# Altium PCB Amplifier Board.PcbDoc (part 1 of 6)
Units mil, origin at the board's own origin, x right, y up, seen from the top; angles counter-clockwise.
Board outline 6000 x 2640 mil, 6 copper layers (Top Layer, GND, VCC, BASES, GND (Plane3), Bottom Layer), stack 63.9 mil thick; 884 components, 484 nets, 2029 pads, 464 vias.
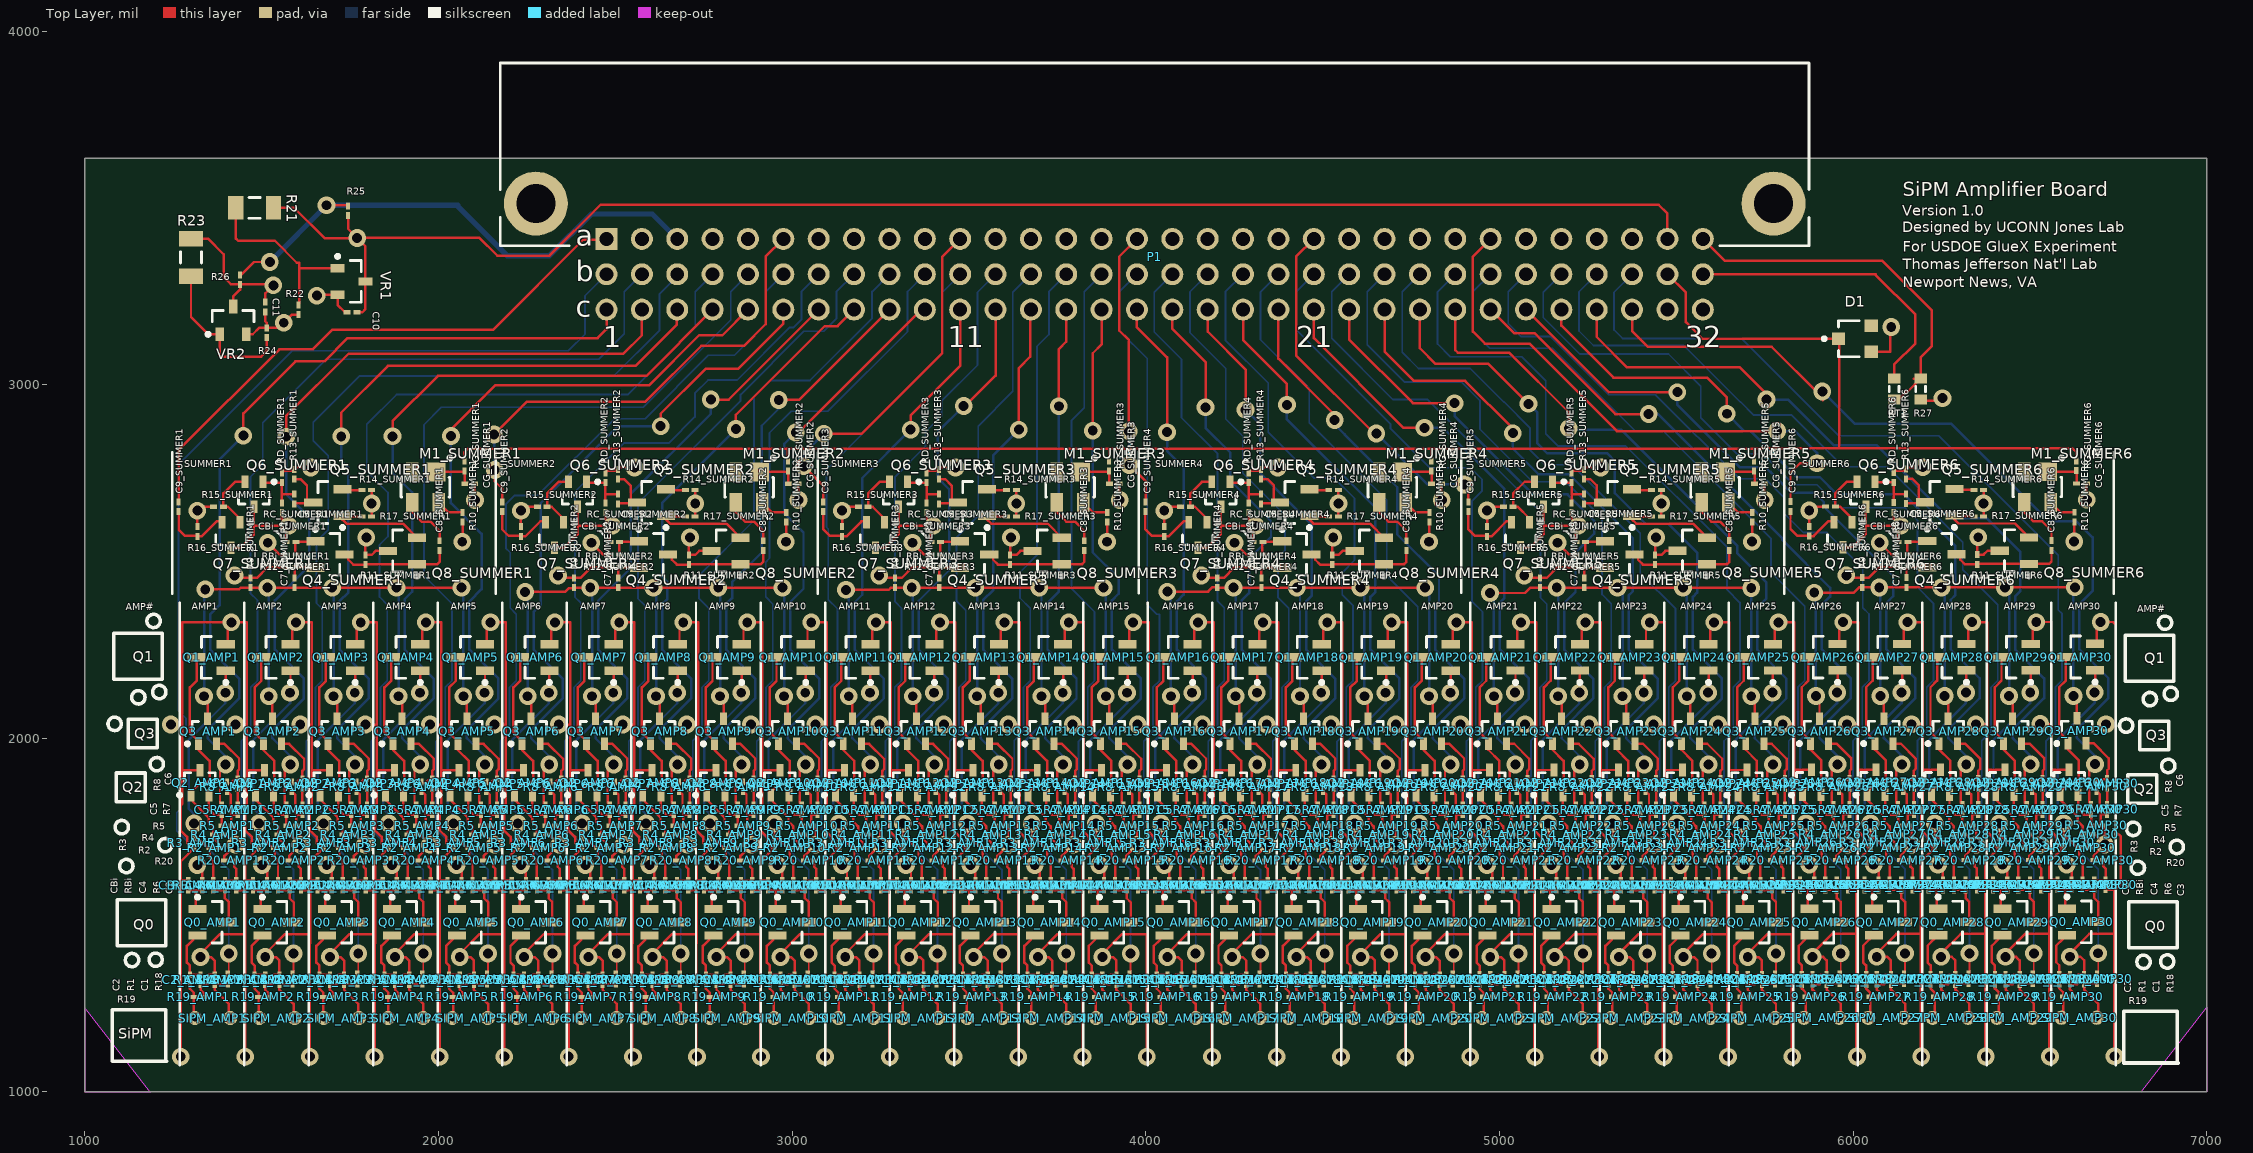
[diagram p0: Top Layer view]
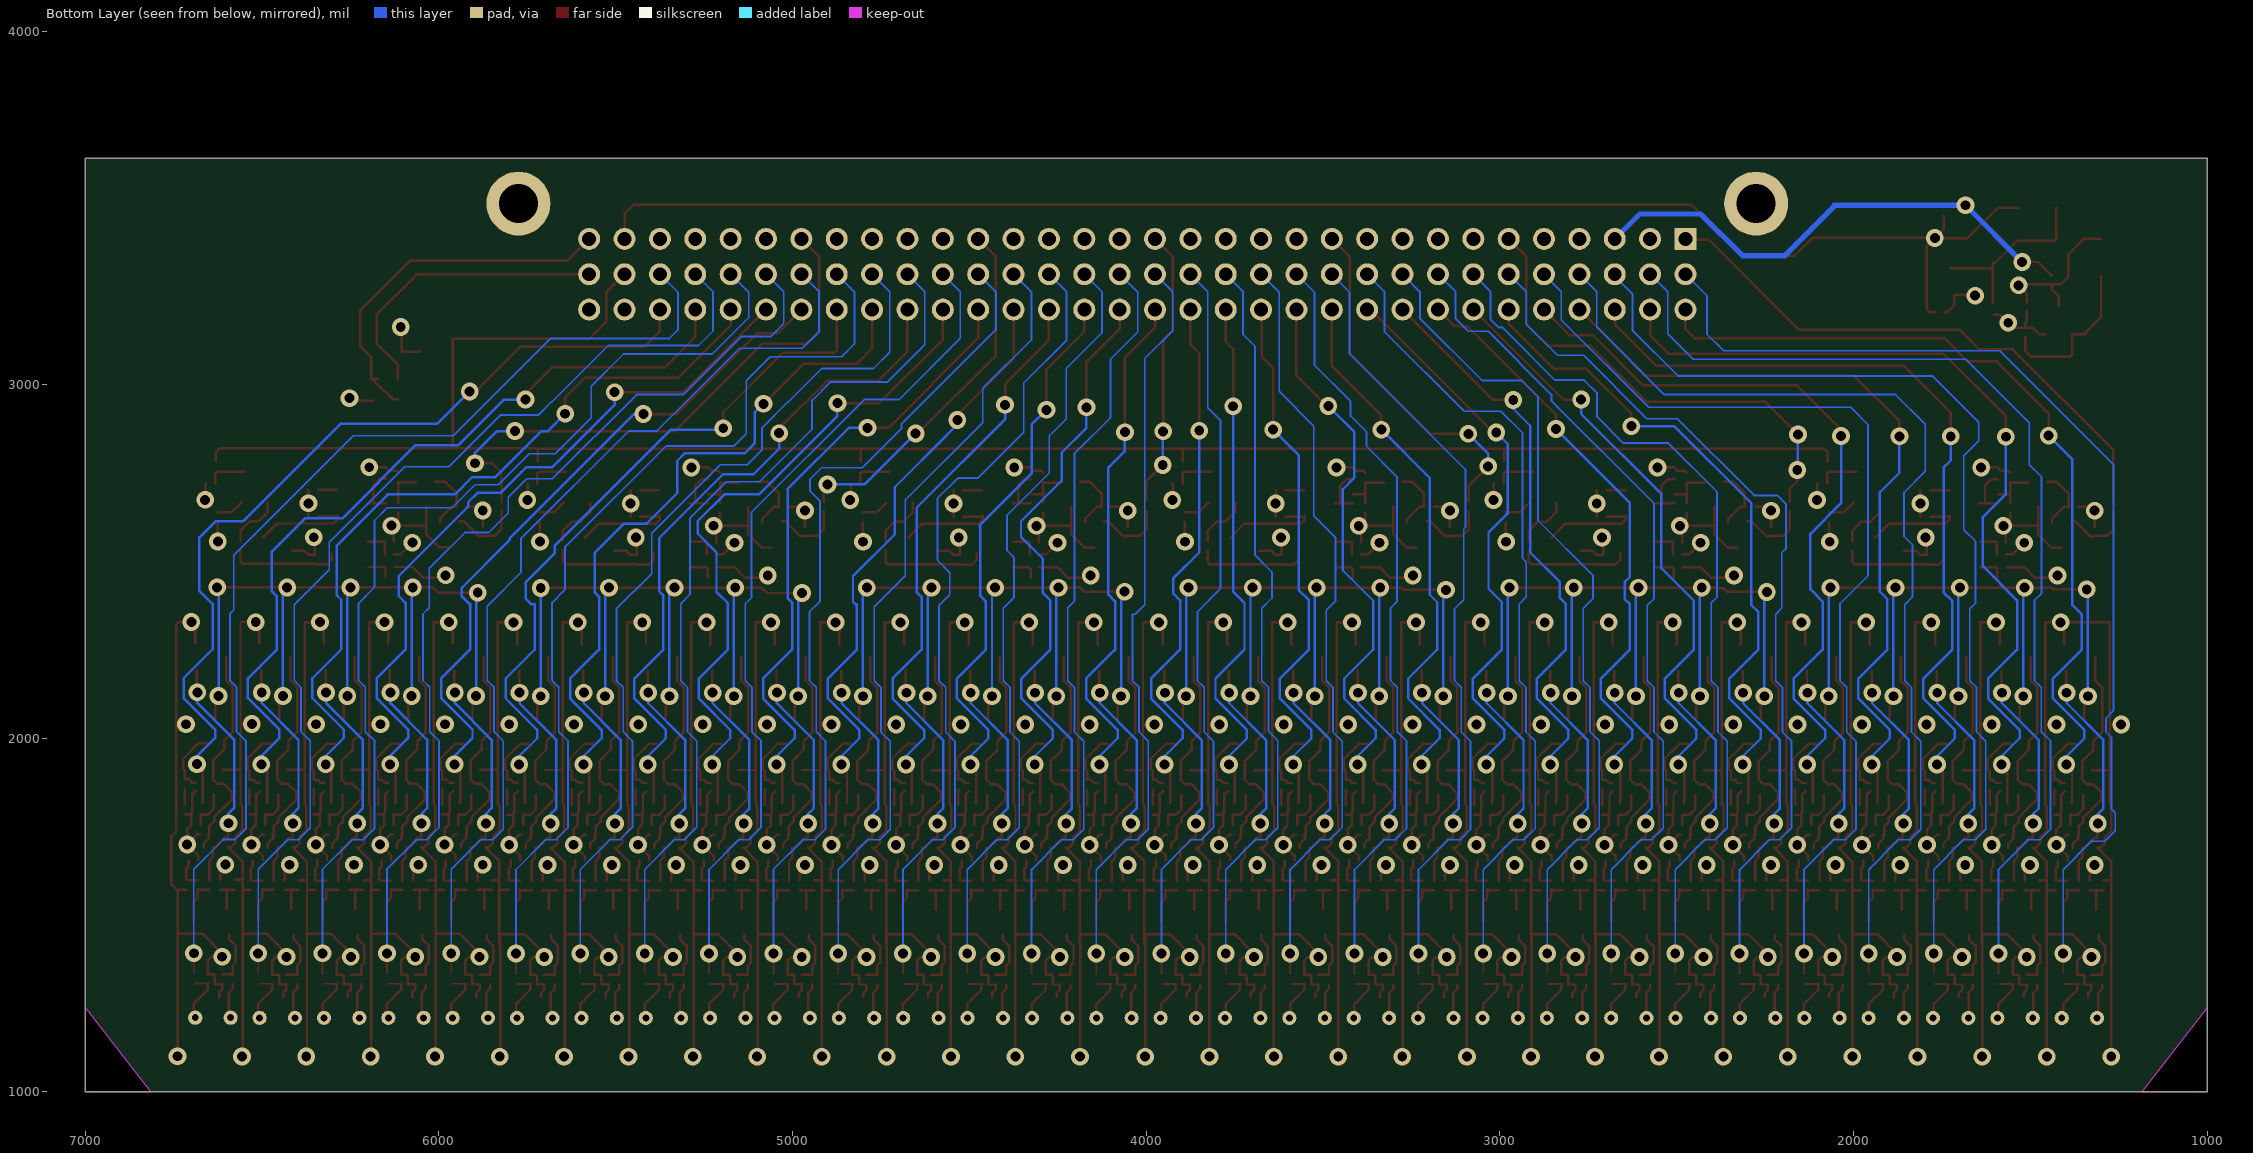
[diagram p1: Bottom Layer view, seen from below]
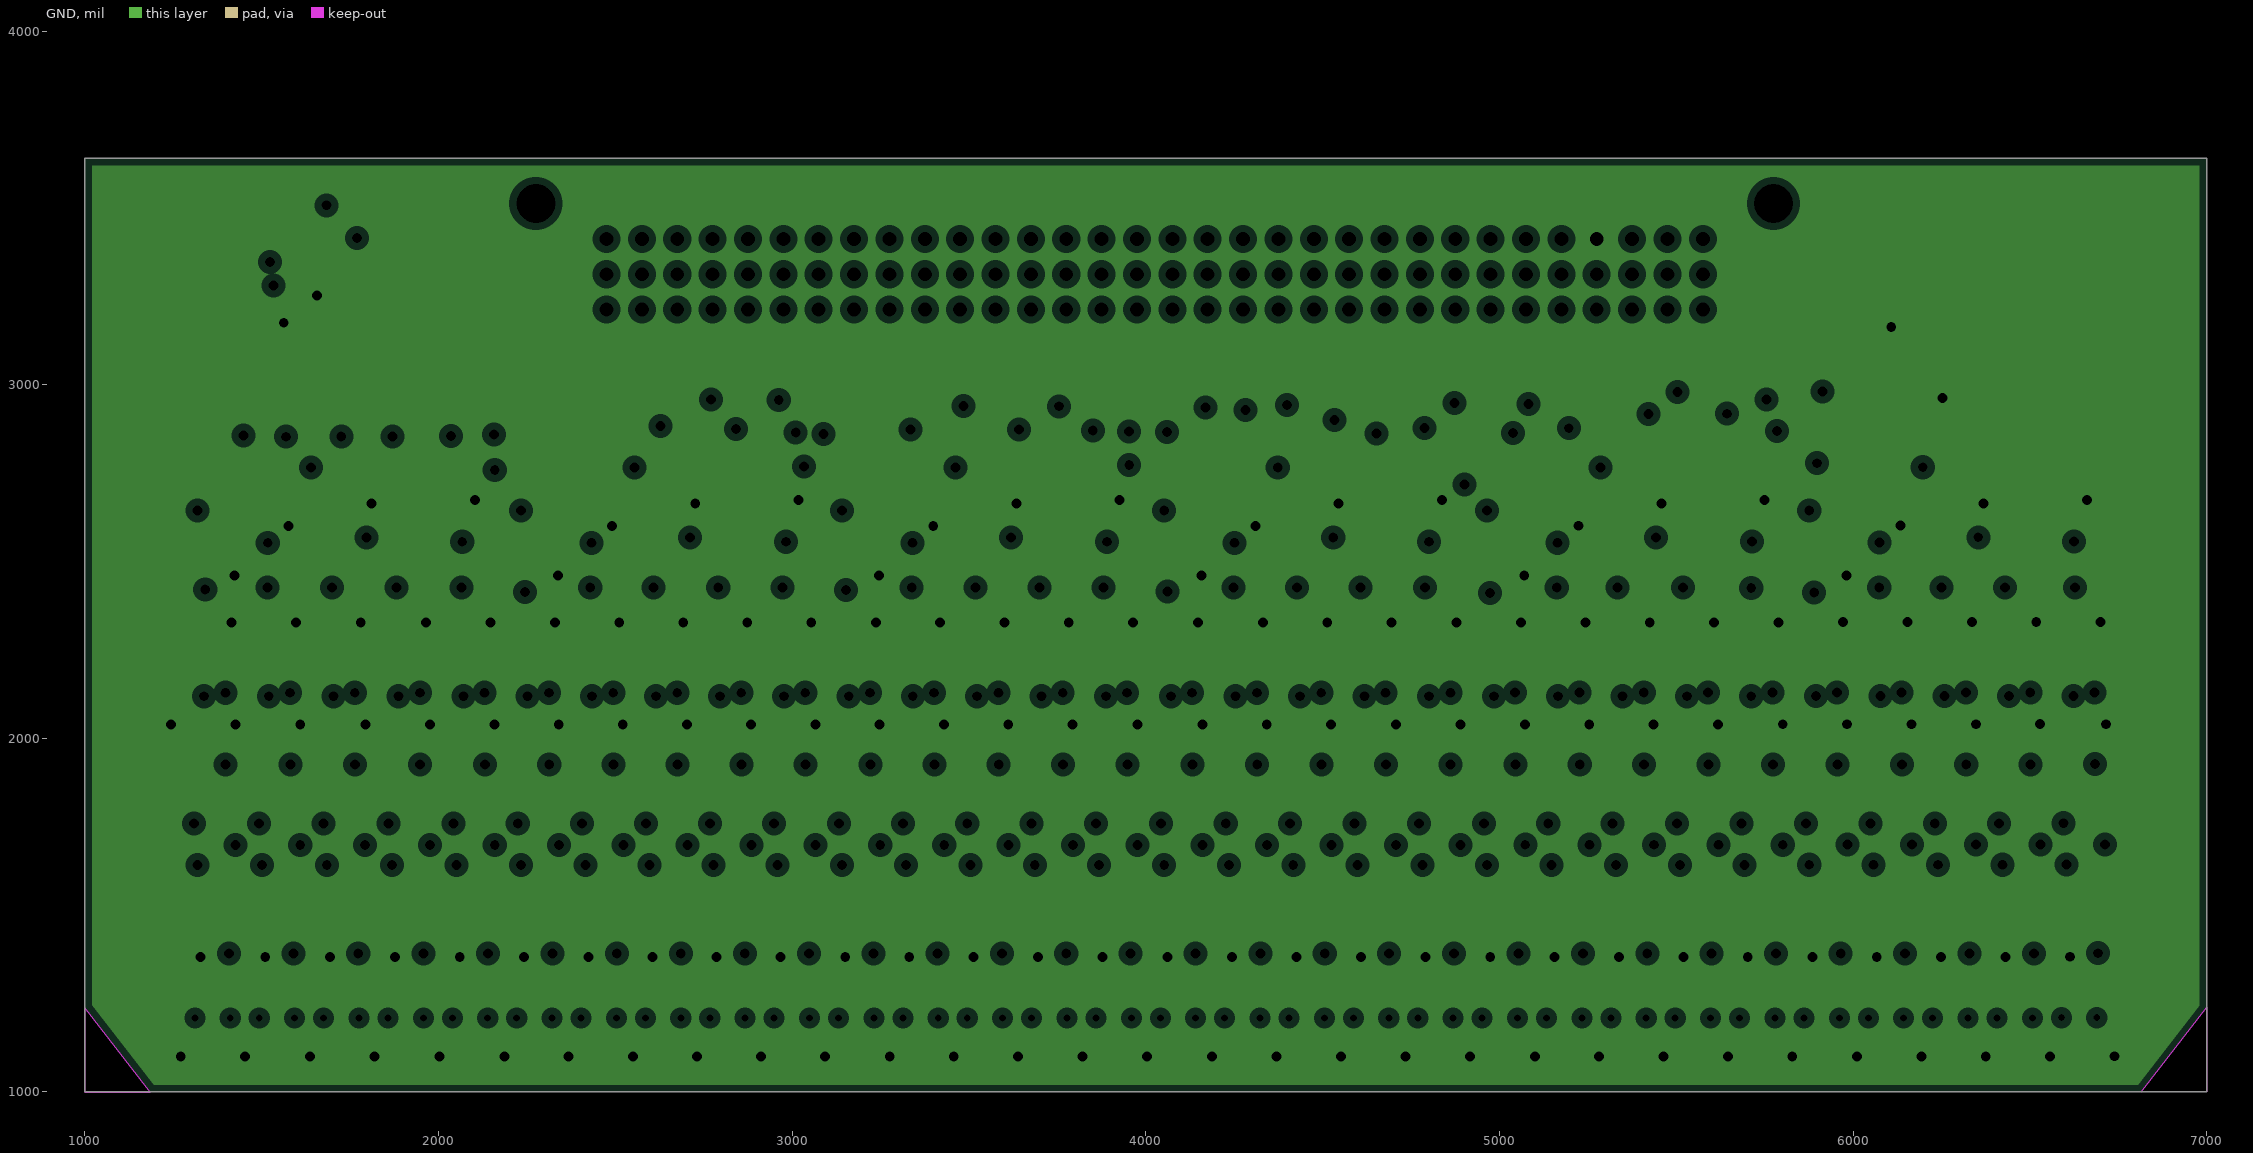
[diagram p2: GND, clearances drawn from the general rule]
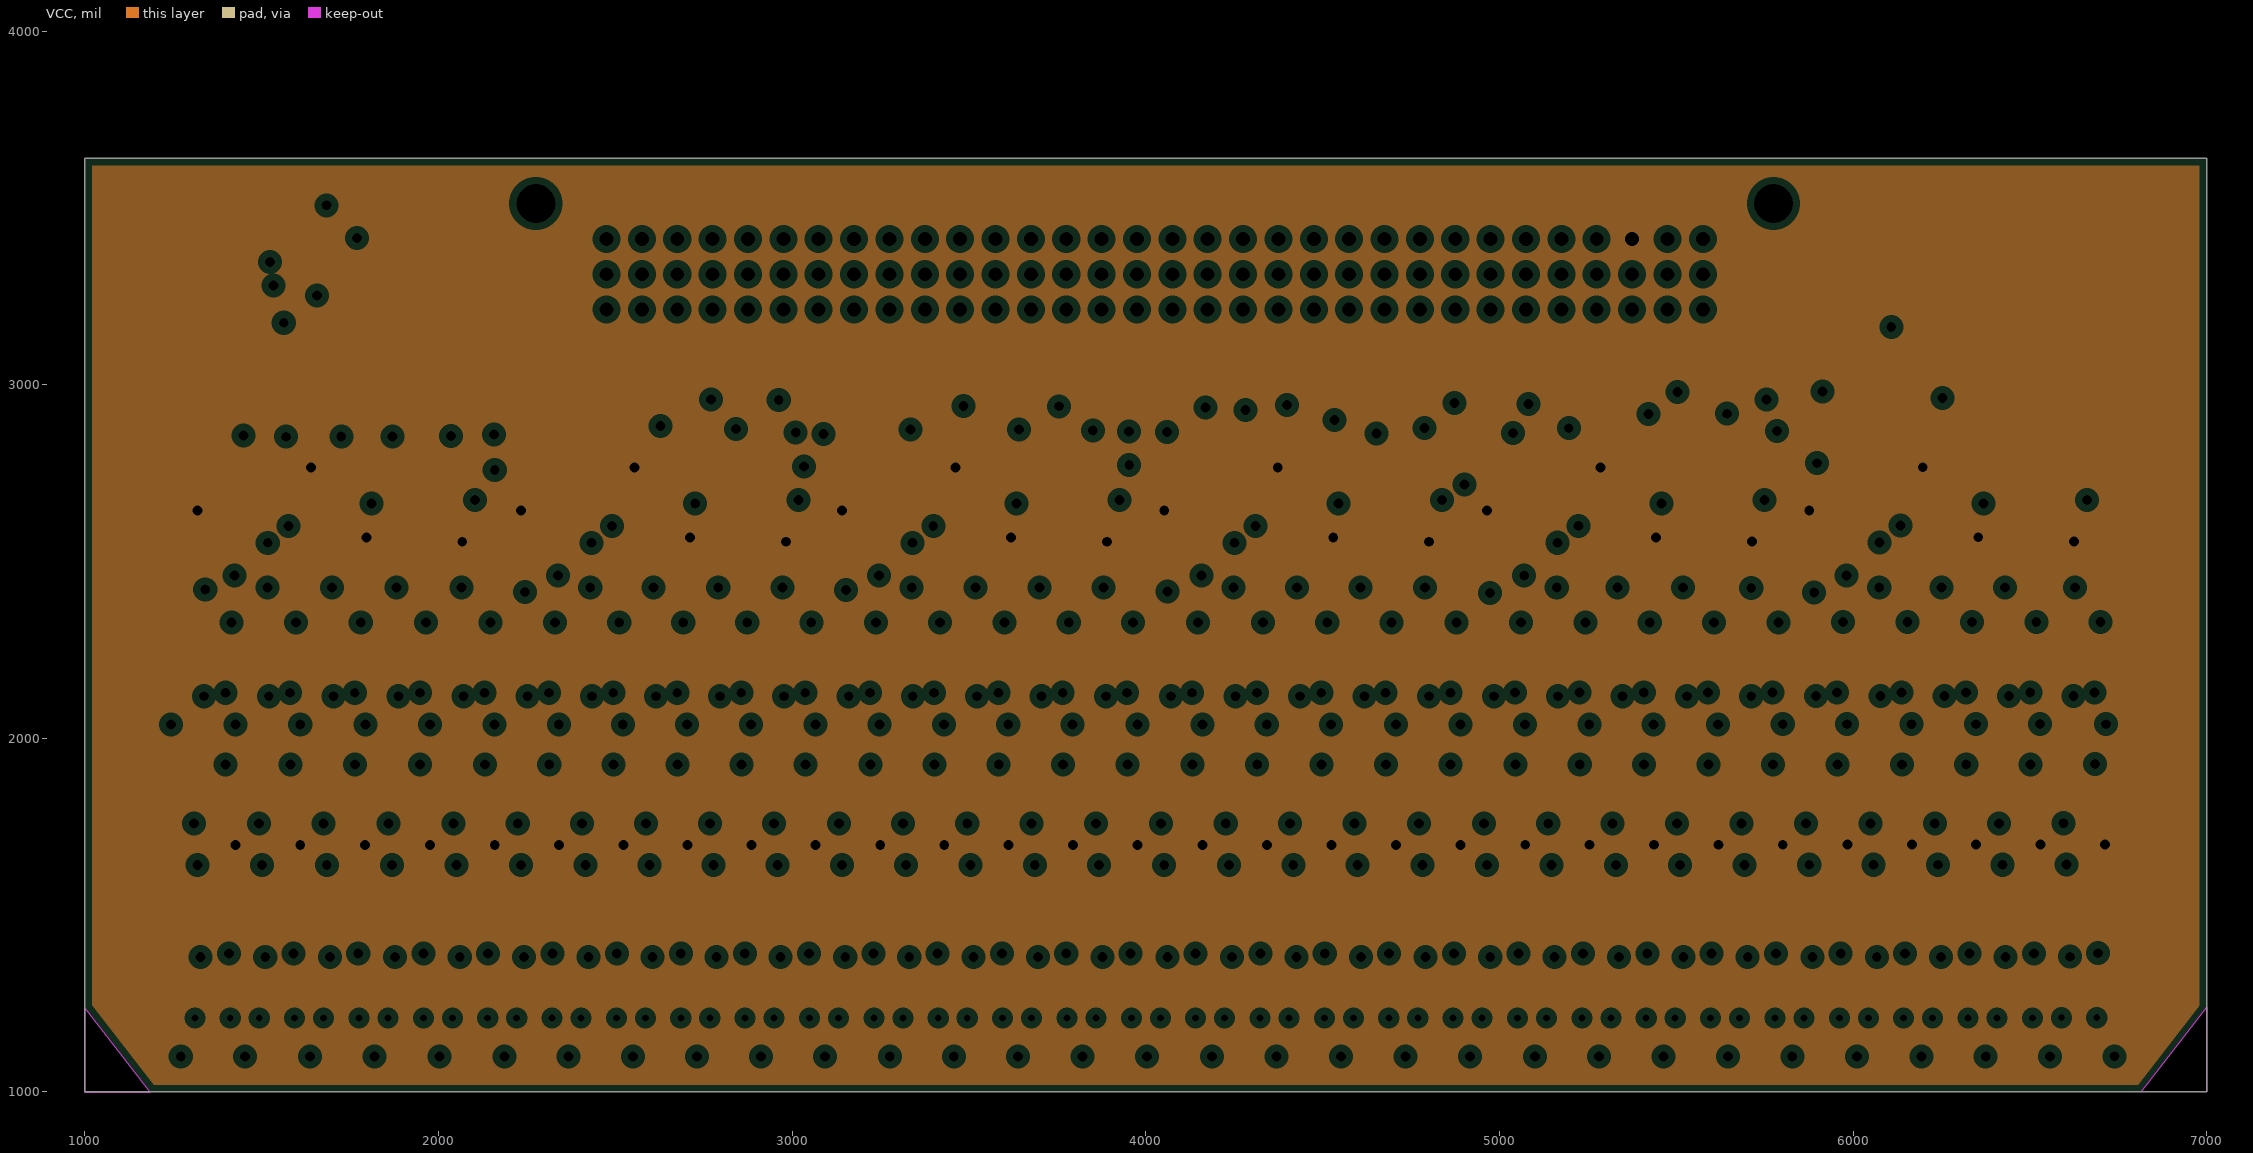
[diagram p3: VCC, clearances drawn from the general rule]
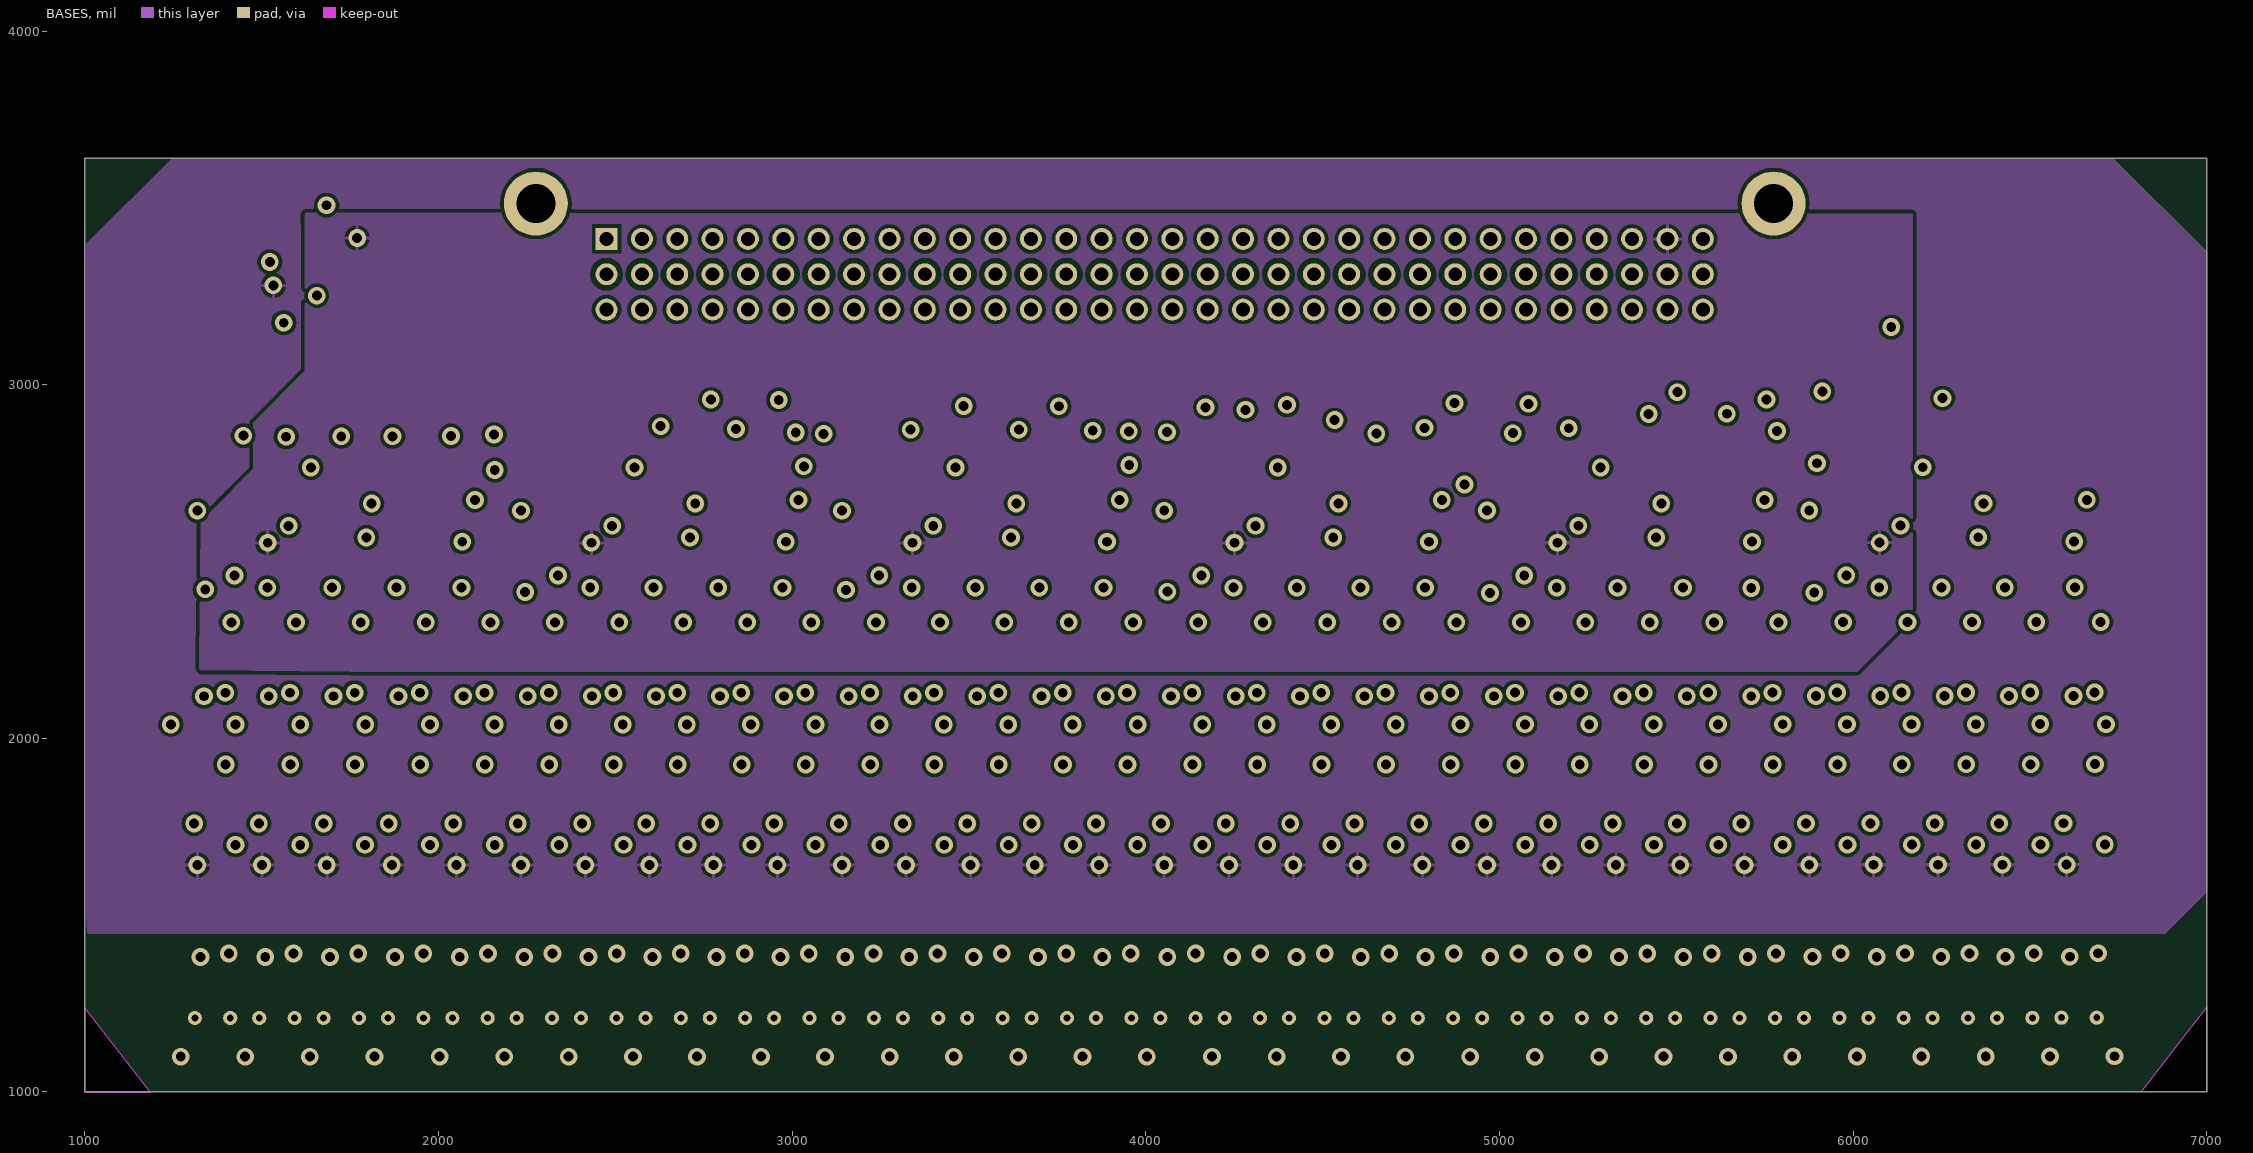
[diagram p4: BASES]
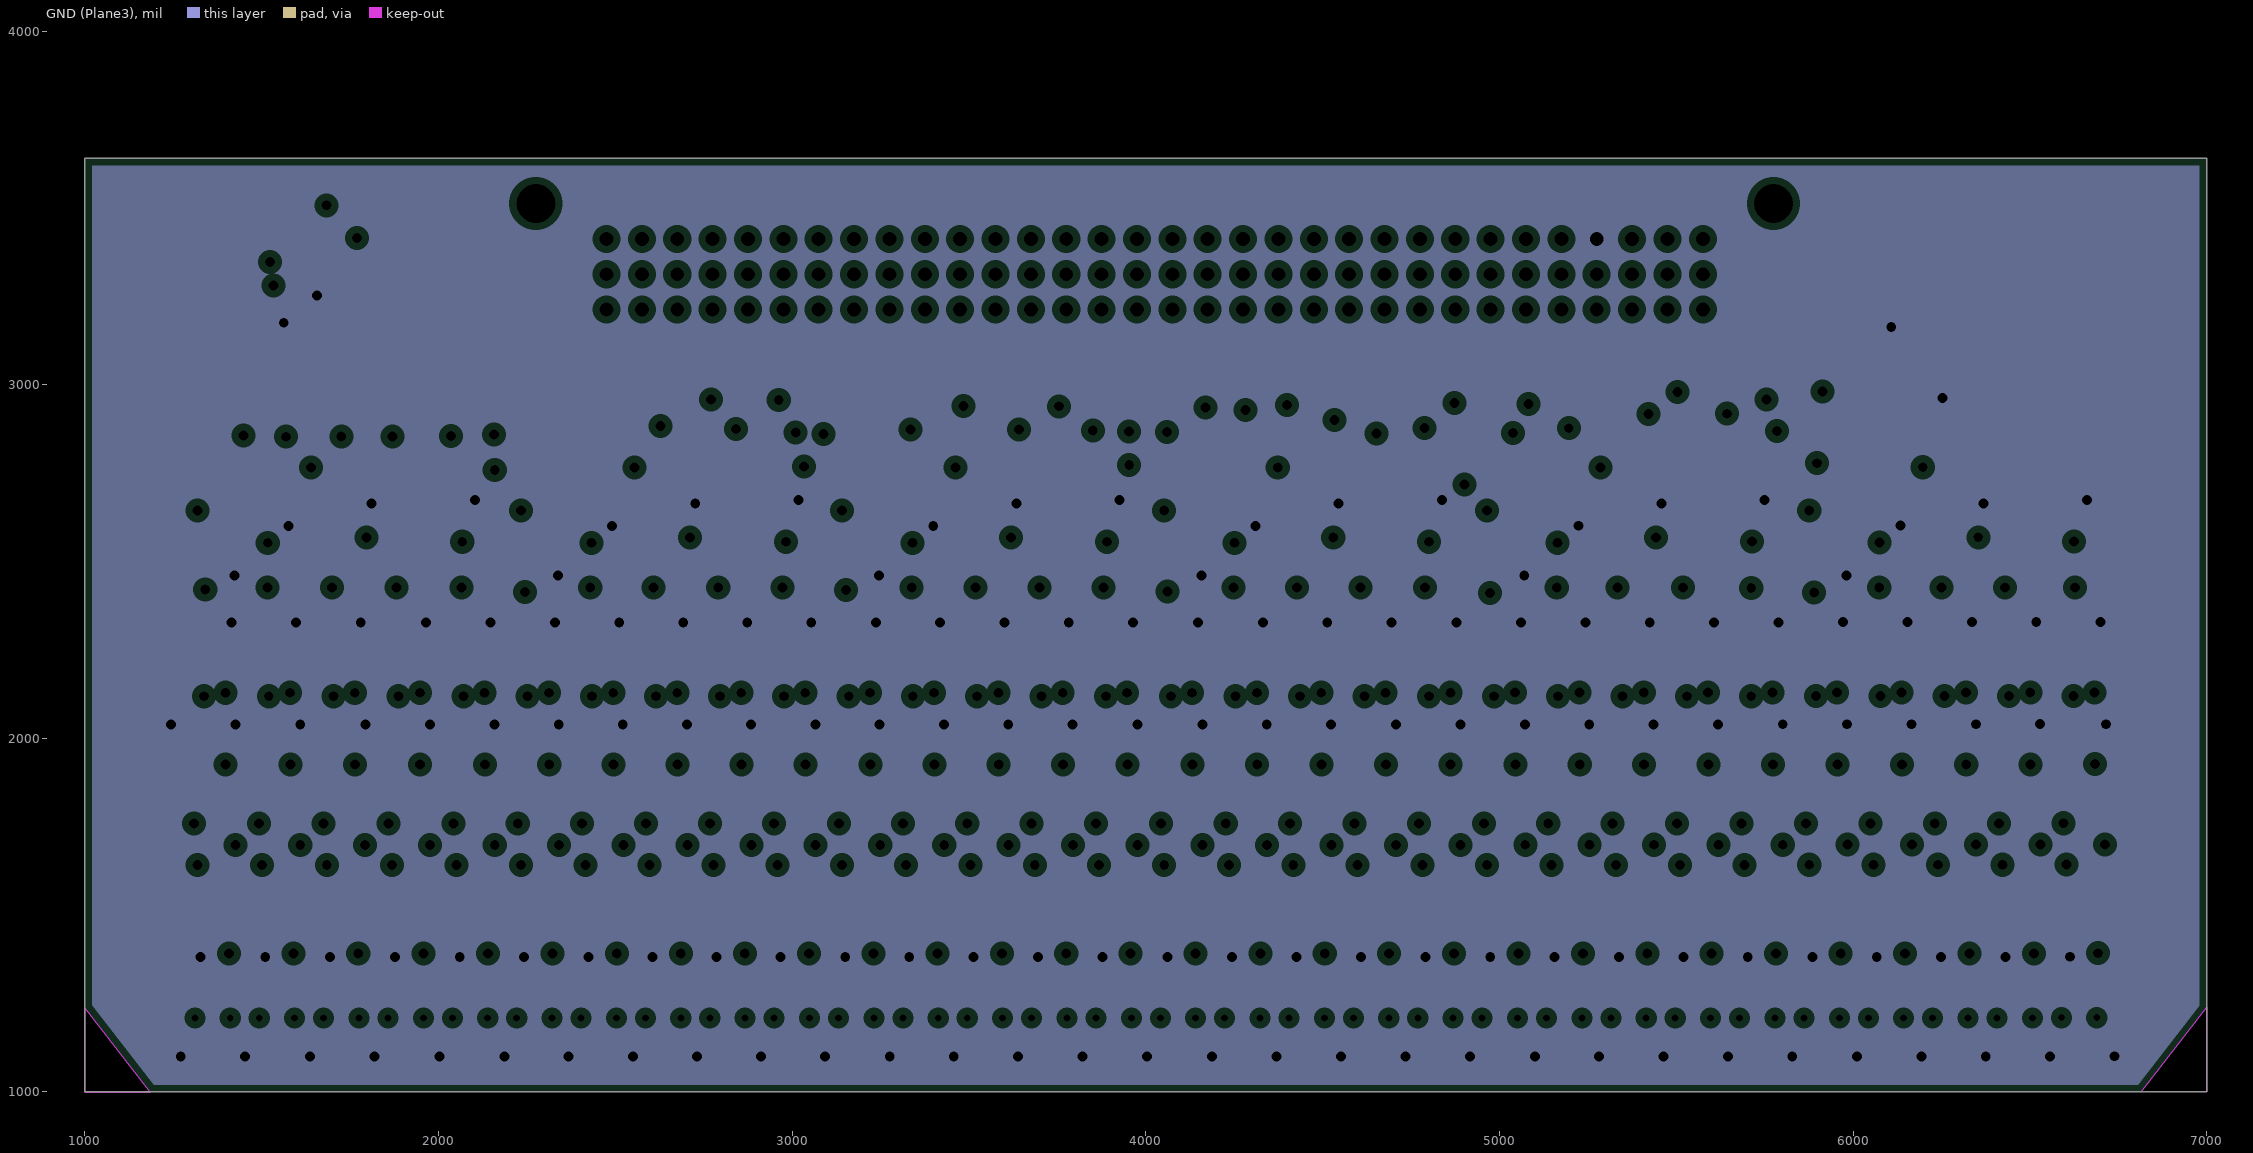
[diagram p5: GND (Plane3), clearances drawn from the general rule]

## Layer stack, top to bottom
Top Layer: signal copper 1.4
Dielectric: prepreg 5.1, FR-4, Dk 4.8
GND: plane copper 1.4, net GND
Dielectric: core 12.6, FR-4, Dk 4.8
VCC: plane copper 1.4, net VCC
Dielectric: prepreg 12.6, FR-4, Dk 4.8
BASES: signal copper 1.4
Dielectric: core 12.6, FR-4, Dk 4.8
GND (Plane3): plane copper 1.4, net GND
Dielectric: prepreg 12.6, FR-4, Dk 4.8
Bottom Layer: signal copper 1.4

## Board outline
1000,1000 7000,1000 7000,3640 1000,3640
cut-out: 1000,1238.5 1000,999.5 1185,999.5
cut-out: 7000.5,1239 7000.5,1000 6815.5,1000

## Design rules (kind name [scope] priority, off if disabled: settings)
Clearance Clearance_0201 [(HasFootprint('RESC0603L')) vs (HasFootprint('RESC0603L'))] p1: gap=6
Clearance Clearance_BIAS [InNetClass('BIAS')] p2: gap=15
Clearance Clearance_General [All] p3: gap=10
ComponentClearance [All] p1: gap=10 collisioncheckmode=3 verticalgap=10
HoleSize [All] p1: absolutevalues=TRUE maxlimit=120 minlimit=1 maxpercent=80.000 minpercent=20.000
PlaneClearance [All] p1: clearance=20
PlaneConnect [All] p1: planeconnectstyle=Relief reliefexpansion=20 reliefentries=4 reliefconductorwidth=10 reliefairgap=10
PolygonConnect [All] p1: connectstyle=Relief reliefconductorwidth=10 reliefentries=4 polygonreliefangle="90 Angle"
RoomDefinition THERMAL [InComponentClass('THERMAL')] p1: confinementstyle=ConfineIn formatcopy=TRUE lockcomponents=FALSE outline 6064,2900 6289,2900 6289,3110 6064,3110
RoomDefinition VREF [InComponentClass('VREF')] p2: confinementstyle=ConfineIn formatcopy=TRUE lockcomponents=FALSE outline 1207,3072 1894,3072 1894,3561 1207,3561
RoomDefinition AMP28 [InComponentClass('AMP28')] p3: confinementstyle=ConfineIn formatcopy=TRUE lockcomponents=FALSE outline 6164,1074.57 6384,1074.57 6384,2392.57 6164,2392.57
RoomDefinition AMP27 [InComponentClass('AMP27')] p4: confinementstyle=ConfineIn formatcopy=TRUE lockcomponents=FALSE outline 5982,1074.57 6202,1074.57 6202,2392.57 5982,2392.57
RoomDefinition AMP26 [InComponentClass('AMP26')] p5: confinementstyle=ConfineIn formatcopy=TRUE lockcomponents=FALSE outline 5800,1074.57 6020,1074.57 6020,2392.57 5800,2392.57
RoomDefinition AMP25 [InComponentClass('AMP25')] p6: confinementstyle=ConfineIn formatcopy=TRUE lockcomponents=FALSE outline 5617,1074.1 5837,1074.1 5837,2392.1 5617,2392.1
RoomDefinition AMP24 [InComponentClass('AMP24')] p7: confinementstyle=ConfineIn formatcopy=TRUE lockcomponents=FALSE outline 5435,1074.1 5655,1074.1 5655,2392.1 5435,2392.1
RoomDefinition AMP23 [InComponentClass('AMP23')] p8: confinementstyle=ConfineIn formatcopy=TRUE lockcomponents=FALSE outline 5253,1074.1 5473,1074.1 5473,2392.1 5253,2392.1
RoomDefinition AMP22 [InComponentClass('AMP22')] p9: confinementstyle=ConfineIn formatcopy=TRUE lockcomponents=FALSE outline 5071,1074.1 5291,1074.1 5291,2392.1 5071,2392.1
RoomDefinition AMP21 [InComponentClass('AMP21')] p10: confinementstyle=ConfineIn formatcopy=TRUE lockcomponents=FALSE outline 4889,1074.1 5109,1074.1 5109,2392.1 4889,2392.1
RoomDefinition AMP20 [InComponentClass('AMP20')] p11: confinementstyle=ConfineIn formatcopy=TRUE lockcomponents=FALSE outline 4706,1074 4926,1074 4926,2392 4706,2392
RoomDefinition AMP19 [InComponentClass('AMP19')] p12: confinementstyle=ConfineIn formatcopy=TRUE lockcomponents=FALSE outline 4523,1074 4743,1074 4743,2392 4523,2392
RoomDefinition AMP18 [InComponentClass('AMP18')] p13: confinementstyle=ConfineIn formatcopy=TRUE lockcomponents=FALSE outline 4341,1074 4561,1074 4561,2392 4341,2392
RoomDefinition AMP17 [InComponentClass('AMP17')] p14: confinementstyle=ConfineIn formatcopy=TRUE lockcomponents=FALSE outline 4159,1074 4379,1074 4379,2392 4159,2392
RoomDefinition AMP16 [InComponentClass('AMP16')] p15: confinementstyle=ConfineIn formatcopy=TRUE lockcomponents=FALSE outline 3976,1074 4196,1074 4196,2392 3976,2392
RoomDefinition AMP15 [InComponentClass('AMP15')] p16: confinementstyle=ConfineIn formatcopy=TRUE lockcomponents=FALSE outline 3792,1074 4012,1074 4012,2392 3792,2392
RoomDefinition AMP14 [InComponentClass('AMP14')] p17: confinementstyle=ConfineIn formatcopy=TRUE lockcomponents=FALSE outline 3610,1074 3830,1074 3830,2392 3610,2392
RoomDefinition AMP13 [InComponentClass('AMP13')] p18: confinementstyle=ConfineIn formatcopy=TRUE lockcomponents=FALSE outline 3428,1074 3648,1074 3648,2392 3428,2392
RoomDefinition AMP12 [InComponentClass('AMP12')] p19: confinementstyle=ConfineIn formatcopy=TRUE lockcomponents=FALSE outline 3246,1074 3466,1074 3466,2392 3246,2392
RoomDefinition AMP11 [InComponentClass('AMP11')] p20: confinementstyle=ConfineIn formatcopy=TRUE lockcomponents=FALSE outline 3065,1074 3285,1074 3285,2392 3065,2392
RoomDefinition AMP10 [InComponentClass('AMP10')] p21: confinementstyle=ConfineIn formatcopy=TRUE lockcomponents=FALSE outline 2882,1074 3102,1074 3102,2392 2882,2392
RoomDefinition AMP9 [InComponentClass('AMP9')] p22: confinementstyle=ConfineIn formatcopy=TRUE lockcomponents=FALSE outline 2701,1074 2921,1074 2921,2392 2701,2392
RoomDefinition AMP8 [InComponentClass('AMP8')] p23: confinementstyle=ConfineIn formatcopy=TRUE lockcomponents=FALSE outline 2520,1074 2740,1074 2740,2392 2520,2392
RoomDefinition AMP7 [InComponentClass('AMP7')] p24: confinementstyle=ConfineIn formatcopy=TRUE lockcomponents=FALSE outline 2339,1074 2559,1074 2559,2392 2339,2392
RoomDefinition AMP6 [InComponentClass('AMP6')] p25: confinementstyle=ConfineIn formatcopy=TRUE lockcomponents=FALSE outline 2157,1074 2377,1074 2377,2392 2157,2392
RoomDefinition AMP5 [InComponentClass('AMP5')] p26: confinementstyle=ConfineIn formatcopy=TRUE lockcomponents=FALSE outline 1975,1074 2195,1074 2195,2392 1975,2392
RoomDefinition AMP4 [InComponentClass('AMP4')] p27: confinementstyle=ConfineIn formatcopy=TRUE lockcomponents=FALSE outline 1792,1074 2012,1074 2012,2392 1792,2392
RoomDefinition AMP3 [InComponentClass('AMP3')] p28: confinementstyle=ConfineIn formatcopy=TRUE lockcomponents=FALSE outline 1608,1074 1828,1074 1828,2392 1608,2392
RoomDefinition AMP2 [InComponentClass('AMP2')] p29: confinementstyle=ConfineIn formatcopy=TRUE lockcomponents=TRUE outline 1425,1074 1645,1074 1645,2392 1425,2392
RoomDefinition AMP1 [InComponentClass('AMP1')] p30: confinementstyle=ConfineIn formatcopy=TRUE lockcomponents=FALSE outline 1242,1074 1462,1074 1462,2392 1242,2392
RoomDefinition AMP29 [InComponentClass('AMP29')] p31: confinementstyle=ConfineIn formatcopy=TRUE lockcomponents=FALSE outline 6346,1074.57 6566,1074.57 6566,2392.57 6346,2392.57
RoomDefinition SUMMER6 [InComponentClass('SUMMER6')] p32: confinementstyle=ConfineIn formatcopy=TRUE lockcomponents=FALSE outline 5800,2392.57 6753,2392.57 6753,2818.57 5800,2818.57
RoomDefinition SUMMER5 [InComponentClass('SUMMER5')] p33: confinementstyle=ConfineIn formatcopy=TRUE lockcomponents=FALSE outline 4889,2392.1 5842,2392.1 5842,2818.1 4889,2818.1
RoomDefinition SUMMER4 [InComponentClass('SUMMER4')] p34: confinementstyle=ConfineIn formatcopy=TRUE lockcomponents=FALSE outline 3976,2392 4929,2392 4929,2818 3976,2818
RoomDefinition SUMMER3 [InComponentClass('SUMMER3')] p35: confinementstyle=ConfineIn formatcopy=TRUE lockcomponents=FALSE outline 3065,2392 4018,2392 4018,2818 3065,2818
RoomDefinition SUMMER2 [InComponentClass('SUMMER2')] p36: confinementstyle=ConfineIn formatcopy=TRUE lockcomponents=FALSE outline 2157,2392 3110,2392 3110,2818 2157,2818
RoomDefinition AMP30 [InComponentClass('AMP30')] p37: confinementstyle=ConfineIn formatcopy=FALSE lockcomponents=FALSE outline 6528,1075 6748,1075 6748,2393 6528,2393
RoomDefinition Main [InComponentClass('Main')] p38: confinementstyle=ConfineIn formatcopy=TRUE lockcomponents=FALSE outline 6141,2982 6141,4174 1926,4174 1926,2982
RoomDefinition SUMMER1 [InComponentClass('SUMMER1')] p39: confinementstyle=ConfineIn formatcopy=TRUE lockcomponents=FALSE outline 1242,2392 2195,2392 2195,2818 1242,2818
RoutingVias [All] p1: holewidth=28 width=50 viastyle="Through Hole" minholewidth=28 minwidth=50 maxholewidth=28 maxwidth=50
SolderMaskExpansion [All] p1: expansion=4
TestPointUsage [All] p1: valid=0 allowmultiple=FALSE
Testpoint [All] p1: side=15 testpointundercomponent=TRUE minsize=40 maxsize=100 preferedsize=60 minholesize=0 maxholesize=40 preferedholesize=32 testpointgrid=1 style=1023 order=0123456789
Width Width_BIAS [InNetClass('BIAS')] p1: maxlimit=10 minlimit=4 preferedwidth=7
Width Width_+5V [InNet('+5V')] p2: maxlimit=20 minlimit=5.09 preferedwidth=15 midlayer1_minwidth=0 midlayer1_maxwidth=0 midlayer1_prefwidth=0 minimp=50.000000 maximp=60.000000 favimp=50.000000
15 further rules are at their usual default settings.

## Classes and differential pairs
channel class Summer: SUMMER1 SUMMER2 SUMMER3 SUMMER4 SUMMER5 SUMMER6
channel class Amplifier: AMP1 AMP2 AMP3 AMP4 AMP5 AMP6 AMP7 AMP8 AMP9 AMP10 AMP11 AMP12 AMP13 AMP14 AMP15 AMP16 AMP17 AMP18 AMP19 AMP20 AMP21 AMP22 AMP23 AMP24 AMP25 AMP26 AMP27 AMP28 AMP29 AMP30
component class VREF: C10 C11 R21 R22 R23 R24 R25 R26 VR1 VR2
component class SUMMER6: C5_SUMMER6 C7_SUMMER6 C8_SUMMER6 C9_SUMMER6 CBi_SUMMER6 CG_SUMMER6 M1_SUMMER6 Q4_SUMMER6 Q5_SUMMER6 Q6_SUMMER6 Q7_SUMMER6 Q8_SUMMER6 R9_SUMMER6 R10_SUMMER6 R11_SUMMER6 R12_SUMMER6 R13_SUMMER6 R14_SUMMER6 R15_SUMMER6 R16_SUMMER6 R17_SUMMER6 RBi_SUMMER6 RC_SUMMER6 RD_SUMMER6 RG_SUMMER6
component class SUMMER5: C5_SUMMER5 C7_SUMMER5 C8_SUMMER5 C9_SUMMER5 CBi_SUMMER5 CG_SUMMER5 M1_SUMMER5 Q4_SUMMER5 Q5_SUMMER5 Q6_SUMMER5 Q7_SUMMER5 Q8_SUMMER5 R9_SUMMER5 R10_SUMMER5 R11_SUMMER5 R12_SUMMER5 R13_SUMMER5 R14_SUMMER5 R15_SUMMER5 R16_SUMMER5 R17_SUMMER5 RBi_SUMMER5 RC_SUMMER5 RD_SUMMER5 RG_SUMMER5
component class SUMMER4: C5_SUMMER4 C7_SUMMER4 C8_SUMMER4 C9_SUMMER4 CBi_SUMMER4 CG_SUMMER4 M1_SUMMER4 Q4_SUMMER4 Q5_SUMMER4 Q6_SUMMER4 Q7_SUMMER4 Q8_SUMMER4 R9_SUMMER4 R10_SUMMER4 R11_SUMMER4 R12_SUMMER4 R13_SUMMER4 R14_SUMMER4 R15_SUMMER4 R16_SUMMER4 R17_SUMMER4 RBi_SUMMER4 RC_SUMMER4 RD_SUMMER4 RG_SUMMER4
component class SUMMER3: C5_SUMMER3 C7_SUMMER3 C8_SUMMER3 C9_SUMMER3 CBi_SUMMER3 CG_SUMMER3 M1_SUMMER3 Q4_SUMMER3 Q5_SUMMER3 Q6_SUMMER3 Q7_SUMMER3 Q8_SUMMER3 R9_SUMMER3 R10_SUMMER3 R11_SUMMER3 R12_SUMMER3 R13_SUMMER3 R14_SUMMER3 R15_SUMMER3 R16_SUMMER3 R17_SUMMER3 RBi_SUMMER3 RC_SUMMER3 RD_SUMMER3 RG_SUMMER3
component class SUMMER2: C5_SUMMER2 C7_SUMMER2 C8_SUMMER2 C9_SUMMER2 CBi_SUMMER2 CG_SUMMER2 M1_SUMMER2 Q4_SUMMER2 Q5_SUMMER2 Q6_SUMMER2 Q7_SUMMER2 Q8_SUMMER2 R9_SUMMER2 R10_SUMMER2 R11_SUMMER2 R12_SUMMER2 R13_SUMMER2 R14_SUMMER2 R15_SUMMER2 R16_SUMMER2 R17_SUMMER2 RBi_SUMMER2 RC_SUMMER2 RD_SUMMER2 RG_SUMMER2
component class SUMMER1: C5_SUMMER1 C7_SUMMER1 C8_SUMMER1 C9_SUMMER1 CBi_SUMMER1 CG_SUMMER1 M1_SUMMER1 Q4_SUMMER1 Q5_SUMMER1 Q6_SUMMER1 Q7_SUMMER1 Q8_SUMMER1 R9_SUMMER1 R10_SUMMER1 R11_SUMMER1 R12_SUMMER1 R13_SUMMER1 R14_SUMMER1 R15_SUMMER1 R16_SUMMER1 R17_SUMMER1 RBi_SUMMER1 RC_SUMMER1 RD_SUMMER1 RG_SUMMER1
component class Main: D1 P1
component class AMP30: C1_AMP30 C2_AMP30 C3_AMP30 C4_AMP30 C5_AMP30 C6_AMP30 CBi_AMP30 Q0_AMP30 Q1_AMP30 Q2_AMP30 Q3_AMP30 R1_AMP30 R2_AMP30 R3_AMP30 R4_AMP30 R5_AMP30 R6_AMP30 R7_AMP30 R8_AMP30 R18_AMP30 R19_AMP30 R20_AMP30 RBi_AMP30 SIPM_AMP30
component class AMP29: C1_AMP29 C2_AMP29 C3_AMP29 C4_AMP29 C5_AMP29 C6_AMP29 CBi_AMP29 Q0_AMP29 Q1_AMP29 Q2_AMP29 Q3_AMP29 R1_AMP29 R2_AMP29 R3_AMP29 R4_AMP29 R5_AMP29 R6_AMP29 R7_AMP29 R8_AMP29 R18_AMP29 R19_AMP29 R20_AMP29 RBi_AMP29 SIPM_AMP29
component class AMP28: C1_AMP28 C2_AMP28 C3_AMP28 C4_AMP28 C5_AMP28 C6_AMP28 CBi_AMP28 Q0_AMP28 Q1_AMP28 Q2_AMP28 Q3_AMP28 R1_AMP28 R2_AMP28 R3_AMP28 R4_AMP28 R5_AMP28 R6_AMP28 R7_AMP28 R8_AMP28 R18_AMP28 R19_AMP28 R20_AMP28 RBi_AMP28 SIPM_AMP28
component class AMP27: C1_AMP27 C2_AMP27 C3_AMP27 C4_AMP27 C5_AMP27 C6_AMP27 CBi_AMP27 Q0_AMP27 Q1_AMP27 Q2_AMP27 Q3_AMP27 R1_AMP27 R2_AMP27 R3_AMP27 R4_AMP27 R5_AMP27 R6_AMP27 R7_AMP27 R8_AMP27 R18_AMP27 R19_AMP27 R20_AMP27 RBi_AMP27 SIPM_AMP27
component class AMP26: C1_AMP26 C2_AMP26 C3_AMP26 C4_AMP26 C5_AMP26 C6_AMP26 CBi_AMP26 Q0_AMP26 Q1_AMP26 Q2_AMP26 Q3_AMP26 R1_AMP26 R2_AMP26 R3_AMP26 R4_AMP26 R5_AMP26 R6_AMP26 R7_AMP26 R8_AMP26 R18_AMP26 R19_AMP26 R20_AMP26 RBi_AMP26 SIPM_AMP26
component class AMP25: C1_AMP25 C2_AMP25 C3_AMP25 C4_AMP25 C5_AMP25 C6_AMP25 CBi_AMP25 Q0_AMP25 Q1_AMP25 Q2_AMP25 Q3_AMP25 R1_AMP25 R2_AMP25 R3_AMP25 R4_AMP25 R5_AMP25 R6_AMP25 R7_AMP25 R8_AMP25 R18_AMP25 R19_AMP25 R20_AMP25 RBi_AMP25 SIPM_AMP25
component class AMP24: C1_AMP24 C2_AMP24 C3_AMP24 C4_AMP24 C5_AMP24 C6_AMP24 CBi_AMP24 Q0_AMP24 Q1_AMP24 Q2_AMP24 Q3_AMP24 R1_AMP24 R2_AMP24 R3_AMP24 R4_AMP24 R5_AMP24 R6_AMP24 R7_AMP24 R8_AMP24 R18_AMP24 R19_AMP24 R20_AMP24 RBi_AMP24 SIPM_AMP24
component class AMP23: C1_AMP23 C2_AMP23 C3_AMP23 C4_AMP23 C5_AMP23 C6_AMP23 CBi_AMP23 Q0_AMP23 Q1_AMP23 Q2_AMP23 Q3_AMP23 R1_AMP23 R2_AMP23 R3_AMP23 R4_AMP23 R5_AMP23 R6_AMP23 R7_AMP23 R8_AMP23 R18_AMP23 R19_AMP23 R20_AMP23 RBi_AMP23 SIPM_AMP23
component class AMP22: C1_AMP22 C2_AMP22 C3_AMP22 C4_AMP22 C5_AMP22 C6_AMP22 CBi_AMP22 Q0_AMP22 Q1_AMP22 Q2_AMP22 Q3_AMP22 R1_AMP22 R2_AMP22 R3_AMP22 R4_AMP22 R5_AMP22 R6_AMP22 R7_AMP22 R8_AMP22 R18_AMP22 R19_AMP22 R20_AMP22 RBi_AMP22 SIPM_AMP22
component class AMP21: C1_AMP21 C2_AMP21 C3_AMP21 C4_AMP21 C5_AMP21 C6_AMP21 CBi_AMP21 Q0_AMP21 Q1_AMP21 Q2_AMP21 Q3_AMP21 R1_AMP21 R2_AMP21 R3_AMP21 R4_AMP21 R5_AMP21 R6_AMP21 R7_AMP21 R8_AMP21 R18_AMP21 R19_AMP21 R20_AMP21 RBi_AMP21 SIPM_AMP21
component class AMP20: C1_AMP20 C2_AMP20 C3_AMP20 C4_AMP20 C5_AMP20 C6_AMP20 CBi_AMP20 Q0_AMP20 Q1_AMP20 Q2_AMP20 Q3_AMP20 R1_AMP20 R2_AMP20 R3_AMP20 R4_AMP20 R5_AMP20 R6_AMP20 R7_AMP20 R8_AMP20 R18_AMP20 R19_AMP20 R20_AMP20 RBi_AMP20 SIPM_AMP20
component class AMP19: C1_AMP19 C2_AMP19 C3_AMP19 C4_AMP19 C5_AMP19 C6_AMP19 CBi_AMP19 Q0_AMP19 Q1_AMP19 Q2_AMP19 Q3_AMP19 R1_AMP19 R2_AMP19 R3_AMP19 R4_AMP19 R5_AMP19 R6_AMP19 R7_AMP19 R8_AMP19 R18_AMP19 R19_AMP19 R20_AMP19 RBi_AMP19 SIPM_AMP19
component class AMP18: C1_AMP18 C2_AMP18 C3_AMP18 C4_AMP18 C5_AMP18 C6_AMP18 CBi_AMP18 Q0_AMP18 Q1_AMP18 Q2_AMP18 Q3_AMP18 R1_AMP18 R2_AMP18 R3_AMP18 R4_AMP18 R5_AMP18 R6_AMP18 R7_AMP18 R8_AMP18 R18_AMP18 R19_AMP18 R20_AMP18 RBi_AMP18 SIPM_AMP18
component class AMP17: C1_AMP17 C2_AMP17 C3_AMP17 C4_AMP17 C5_AMP17 C6_AMP17 CBi_AMP17 Q0_AMP17 Q1_AMP17 Q2_AMP17 Q3_AMP17 R1_AMP17 R2_AMP17 R3_AMP17 R4_AMP17 R5_AMP17 R6_AMP17 R7_AMP17 R8_AMP17 R18_AMP17 R19_AMP17 R20_AMP17 RBi_AMP17 SIPM_AMP17
component class AMP16: C1_AMP16 C2_AMP16 C3_AMP16 C4_AMP16 C5_AMP16 C6_AMP16 CBi_AMP16 Q0_AMP16 Q1_AMP16 Q2_AMP16 Q3_AMP16 R1_AMP16 R2_AMP16 R3_AMP16 R4_AMP16 R5_AMP16 R6_AMP16 R7_AMP16 R8_AMP16 R18_AMP16 R19_AMP16 R20_AMP16 RBi_AMP16 SIPM_AMP16
component class AMP15: C1_AMP15 C2_AMP15 C3_AMP15 C4_AMP15 C5_AMP15 C6_AMP15 CBi_AMP15 Q0_AMP15 Q1_AMP15 Q2_AMP15 Q3_AMP15 R1_AMP15 R2_AMP15 R3_AMP15 R4_AMP15 R5_AMP15 R6_AMP15 R7_AMP15 R8_AMP15 R18_AMP15 R19_AMP15 R20_AMP15 RBi_AMP15 SIPM_AMP15
component class AMP14: C1_AMP14 C2_AMP14 C3_AMP14 C4_AMP14 C5_AMP14 C6_AMP14 CBi_AMP14 Q0_AMP14 Q1_AMP14 Q2_AMP14 Q3_AMP14 R1_AMP14 R2_AMP14 R3_AMP14 R4_AMP14 R5_AMP14 R6_AMP14 R7_AMP14 R8_AMP14 R18_AMP14 R19_AMP14 R20_AMP14 RBi_AMP14 SIPM_AMP14
component class AMP13: C1_AMP13 C2_AMP13 C3_AMP13 C4_AMP13 C5_AMP13 C6_AMP13 CBi_AMP13 Q0_AMP13 Q1_AMP13 Q2_AMP13 Q3_AMP13 R1_AMP13 R2_AMP13 R3_AMP13 R4_AMP13 R5_AMP13 R6_AMP13 R7_AMP13 R8_AMP13 R18_AMP13 R19_AMP13 R20_AMP13 RBi_AMP13 SIPM_AMP13
component class AMP12: C1_AMP12 C2_AMP12 C3_AMP12 C4_AMP12 C5_AMP12 C6_AMP12 CBi_AMP12 Q0_AMP12 Q1_AMP12 Q2_AMP12 Q3_AMP12 R1_AMP12 R2_AMP12 R3_AMP12 R4_AMP12 R5_AMP12 R6_AMP12 R7_AMP12 R8_AMP12 R18_AMP12 R19_AMP12 R20_AMP12 RBi_AMP12 SIPM_AMP12
component class AMP11: C1_AMP11 C2_AMP11 C3_AMP11 C4_AMP11 C5_AMP11 C6_AMP11 CBi_AMP11 Q0_AMP11 Q1_AMP11 Q2_AMP11 Q3_AMP11 R1_AMP11 R2_AMP11 R3_AMP11 R4_AMP11 R5_AMP11 R6_AMP11 R7_AMP11 R8_AMP11 R18_AMP11 R19_AMP11 R20_AMP11 RBi_AMP11 SIPM_AMP11
component class AMP10: C1_AMP10 C2_AMP10 C3_AMP10 C4_AMP10 C5_AMP10 C6_AMP10 CBi_AMP10 Q0_AMP10 Q1_AMP10 Q2_AMP10 Q3_AMP10 R1_AMP10 R2_AMP10 R3_AMP10 R4_AMP10 R5_AMP10 R6_AMP10 R7_AMP10 R8_AMP10 R18_AMP10 R19_AMP10 R20_AMP10 RBi_AMP10 SIPM_AMP10
component class AMP9: C1_AMP9 C2_AMP9 C3_AMP9 C4_AMP9 C5_AMP9 C6_AMP9 CBi_AMP9 Q0_AMP9 Q1_AMP9 Q2_AMP9 Q3_AMP9 R1_AMP9 R2_AMP9 R3_AMP9 R4_AMP9 R5_AMP9 R6_AMP9 R7_AMP9 R8_AMP9 R18_AMP9 R19_AMP9 R20_AMP9 RBi_AMP9 SIPM_AMP9
component class AMP8: C1_AMP8 C2_AMP8 C3_AMP8 C4_AMP8 C5_AMP8 C6_AMP8 CBi_AMP8 Q0_AMP8 Q1_AMP8 Q2_AMP8 Q3_AMP8 R1_AMP8 R2_AMP8 R3_AMP8 R4_AMP8 R5_AMP8 R6_AMP8 R7_AMP8 R8_AMP8 R18_AMP8 R19_AMP8 R20_AMP8 RBi_AMP8 SIPM_AMP8
component class AMP7: C1_AMP7 C2_AMP7 C3_AMP7 C4_AMP7 C5_AMP7 C6_AMP7 CBi_AMP7 Q0_AMP7 Q1_AMP7 Q2_AMP7 Q3_AMP7 R1_AMP7 R2_AMP7 R3_AMP7 R4_AMP7 R5_AMP7 R6_AMP7 R7_AMP7 R8_AMP7 R18_AMP7 R19_AMP7 R20_AMP7 RBi_AMP7 SIPM_AMP7
component class AMP6: C1_AMP6 C2_AMP6 C3_AMP6 C4_AMP6 C5_AMP6 C6_AMP6 CBi_AMP6 Q0_AMP6 Q1_AMP6 Q2_AMP6 Q3_AMP6 R1_AMP6 R2_AMP6 R3_AMP6 R4_AMP6 R5_AMP6 R6_AMP6 R7_AMP6 R8_AMP6 R18_AMP6 R19_AMP6 R20_AMP6 RBi_AMP6 SIPM_AMP6
component class AMP5: C1_AMP5 C2_AMP5 C3_AMP5 C4_AMP5 C5_AMP5 C6_AMP5 CBi_AMP5 Q0_AMP5 Q1_AMP5 Q2_AMP5 Q3_AMP5 R1_AMP5 R2_AMP5 R3_AMP5 R4_AMP5 R5_AMP5 R6_AMP5 R7_AMP5 R8_AMP5 R18_AMP5 R19_AMP5 R20_AMP5 RBi_AMP5 SIPM_AMP5
component class AMP4: C1_AMP4 C2_AMP4 C3_AMP4 C4_AMP4 C5_AMP4 C6_AMP4 CBi_AMP4 Q0_AMP4 Q1_AMP4 Q2_AMP4 Q3_AMP4 R1_AMP4 R2_AMP4 R3_AMP4 R4_AMP4 R5_AMP4 R6_AMP4 R7_AMP4 R8_AMP4 R18_AMP4 R19_AMP4 R20_AMP4 RBi_AMP4 SIPM_AMP4
component class AMP3: C1_AMP3 C2_AMP3 C3_AMP3 C4_AMP3 C5_AMP3 C6_AMP3 CBi_AMP3 Q0_AMP3 Q1_AMP3 Q2_AMP3 Q3_AMP3 R1_AMP3 R2_AMP3 R3_AMP3 R4_AMP3 R5_AMP3 R6_AMP3 R7_AMP3 R8_AMP3 R18_AMP3 R19_AMP3 R20_AMP3 RBi_AMP3 SIPM_AMP3
component class AMP2: C1_AMP2 C2_AMP2 C3_AMP2 C4_AMP2 C5_AMP2 C6_AMP2 CBi_AMP2 Q0_AMP2 Q1_AMP2 Q2_AMP2 Q3_AMP2 R1_AMP2 R2_AMP2 R3_AMP2 R4_AMP2 R5_AMP2 R6_AMP2 R7_AMP2 R8_AMP2 R18_AMP2 R19_AMP2 R20_AMP2 RBi_AMP2 SIPM_AMP2
component class AMP1: C1_AMP1 C2_AMP1 C3_AMP1 C4_AMP1 C5_AMP1 C6_AMP1 CBi_AMP1 Q0_AMP1 Q1_AMP1 Q2_AMP1 Q3_AMP1 R1_AMP1 R2_AMP1 R3_AMP1 R4_AMP1 R5_AMP1 R6_AMP1 R7_AMP1 R8_AMP1 R18_AMP1 R19_AMP1 R20_AMP1 RBi_AMP1 SIPM_AMP1
net class SUMMEDOUT[1..6]: SUMMEDOUT1 SUMMEDOUT2 SUMMEDOUT3 SUMMEDOUT4 SUMMEDOUT5 SUMMEDOUT6
net class SIPMOUT: SIPMOUT1_SUMMER1 SIPMOUT1_SUMMER2 SIPMOUT1_SUMMER3 SIPMOUT1_SUMMER4 SIPMOUT1_SUMMER5 SIPMOUT1_SUMMER6 SIPMOUT2_SUMMER1 SIPMOUT2_SUMMER2 SIPMOUT2_SUMMER3 SIPMOUT2_SUMMER4 SIPMOUT2_SUMMER5 SIPMOUT2_SUMMER6 SIPMOUT3_SUMMER1 SIPMOUT3_SUMMER2 SIPMOUT3_SUMMER3 SIPMOUT3_SUMMER4 SIPMOUT3_SUMMER5 SIPMOUT3_SUMMER6 SIPMOUT4_SUMMER1 SIPMOUT4_SUMMER2 SIPMOUT4_SUMMER3 SIPMOUT4_SUMMER4 SIPMOUT4_SUMMER5 SIPMOUT4_SUMMER6 SIPMOUT5_SUMMER1 SIPMOUT5_SUMMER2 SIPMOUT5_SUMMER3 SIPMOUT5_SUMMER4 SIPMOUT5_SUMMER5 SIPMOUT5_SUMMER6
net class BIAS: BIAS1_SUMMER1 BIAS1_SUMMER2 BIAS1_SUMMER3 BIAS1_SUMMER4 BIAS1_SUMMER5 BIAS1_SUMMER6 BIAS2_SUMMER1 BIAS2_SUMMER2 BIAS2_SUMMER3 BIAS2_SUMMER4 BIAS2_SUMMER5 BIAS2_SUMMER6 BIAS3_SUMMER1 BIAS3_SUMMER2 BIAS3_SUMMER3 BIAS3_SUMMER4 BIAS3_SUMMER5 BIAS3_SUMMER6 BIAS4_SUMMER1 BIAS4_SUMMER2 BIAS4_SUMMER3 BIAS4_SUMMER4 BIAS4_SUMMER5 BIAS4_SUMMER6 BIAS5_SUMMER1 BIAS5_SUMMER2 BIAS5_SUMMER3 BIAS5_SUMMER4 BIAS5_SUMMER5 BIAS5_SUMMER6
component class THERMAL: R27 RT1

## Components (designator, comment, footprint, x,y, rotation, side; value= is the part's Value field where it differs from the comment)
C1_AMP1 "Cap" RESC0603L 1367,1317.78 r90 top (schematic designator C1)
C1_AMP2 "Cap" RESC0603L 1550,1317.78 r90 top (schematic designator C1)
C1_AMP3 "Cap" RESC0603L 1733,1317.78 r90 top (schematic designator C1)
C1_AMP4 "Cap" RESC0603L 1917,1317.78 r90 top (schematic designator C1)
C1_AMP5 "Cap" RESC0603L 2100,1317.78 r90 top (schematic designator C1)
C1_AMP6 "Cap" RESC0603L 2282,1317.78 r90 top (schematic designator C1)
C1_AMP7 "Cap" RESC0603L 2464,1317.78 r90 top (schematic designator C1)
C1_AMP8 "Cap" RESC0603L 2645,1317.78 r90 top (schematic designator C1)
C1_AMP9 "Cap" RESC0603L 2826,1317.78 r90 top (schematic designator C1)
C1_AMP10 "Cap" RESC0603L 3007,1317.78 r90 top (schematic designator C1)
C1_AMP11 "Cap" RESC0603L 3190,1317.78 r90 top (schematic designator C1)
C1_AMP12 "Cap" RESC0603L 3371,1317.78 r90 top (schematic designator C1)
C1_AMP13 "Cap" RESC0603L 3553,1317.78 r90 top (schematic designator C1)
C1_AMP14 "Cap" RESC0603L 3735,1317.78 r90 top (schematic designator C1)
C1_AMP15 "Cap" RESC0603L 3917,1317.78 r90 top (schematic designator C1)
C1_AMP16 "Cap" RESC0603L 4101,1317.78 r90 top (schematic designator C1)
C1_AMP17 "Cap" RESC0603L 4284,1317.78 r90 top (schematic designator C1)
C1_AMP18 "Cap" RESC0603L 4466,1317.78 r90 top (schematic designator C1)
C1_AMP19 "Cap" RESC0603L 4648,1317.78 r90 top (schematic designator C1)
C1_AMP20 "Cap" RESC0603L 4831,1317.78 r90 top (schematic designator C1)
C1_AMP21 "Cap" RESC0603L 5014,1317.88 r90 top (schematic designator C1)
C1_AMP22 "Cap" RESC0603L 5196,1317.88 r90 top (schematic designator C1)
C1_AMP23 "Cap" RESC0603L 5378,1317.88 r90 top (schematic designator C1)
C1_AMP24 "Cap" RESC0603L 5560,1317.88 r90 top (schematic designator C1)
C1_AMP25 "Cap" RESC0603L 5742,1317.88 r90 top (schematic designator C1)
C1_AMP26 "Cap" RESC0603L 5925,1318.35 r90 top (schematic designator C1)
C1_AMP27 "Cap" RESC0603L 6107,1318.35 r90 top (schematic designator C1)
C1_AMP28 "Cap" RESC0603L 6289,1318.35 r90 top (schematic designator C1)
C1_AMP29 "Cap" RESC0603L 6471,1318.35 r90 top (schematic designator C1)
C1_AMP30 "Cap" RESC0603L 6653,1318.78 r90 top (schematic designator C1)
C2_AMP1 "Cap" RESC0603L 1297,1317.78 r90 top (schematic designator C2)
C2_AMP2 "Cap" RESC0603L 1480,1317.78 r90 top (schematic designator C2)
C2_AMP3 "Cap" RESC0603L 1663,1317.78 r90 top (schematic designator C2)
C2_AMP4 "Cap" RESC0603L 1847,1317.78 r90 top (schematic designator C2)
C2_AMP5 "Cap" RESC0603L 2030,1317.78 r90 top (schematic designator C2)
C2_AMP6 "Cap" RESC0603L 2212,1317.78 r90 top (schematic designator C2)
C2_AMP7 "Cap" RESC0603L 2394,1317.78 r90 top (schematic designator C2)
C2_AMP8 "Cap" RESC0603L 2575,1317.78 r90 top (schematic designator C2)
C2_AMP9 "Cap" RESC0603L 2756,1317.78 r90 top (schematic designator C2)
C2_AMP10 "Cap" RESC0603L 2937,1317.78 r90 top (schematic designator C2)
C2_AMP11 "Cap" RESC0603L 3120,1317.78 r90 top (schematic designator C2)
C2_AMP12 "Cap" RESC0603L 3301,1317.78 r90 top (schematic designator C2)
C2_AMP13 "Cap" RESC0603L 3483,1317.78 r90 top (schematic designator C2)
C2_AMP14 "Cap" RESC0603L 3665,1317.78 r90 top (schematic designator C2)
C2_AMP15 "Cap" RESC0603L 3847,1317.78 r90 top (schematic designator C2)
C2_AMP16 "Cap" RESC0603L 4031,1317.78 r90 top (schematic designator C2)
C2_AMP17 "Cap" RESC0603L 4214,1317.78 r90 top (schematic designator C2)
C2_AMP18 "Cap" RESC0603L 4396,1317.78 r90 top (schematic designator C2)
C2_AMP19 "Cap" RESC0603L 4578,1317.78 r90 top (schematic designator C2)
C2_AMP20 "Cap" RESC0603L 4761,1317.78 r90 top (schematic designator C2)
C2_AMP21 "Cap" RESC0603L 4944,1317.88 r90 top (schematic designator C2)
C2_AMP22 "Cap" RESC0603L 5126,1317.88 r90 top (schematic designator C2)
C2_AMP23 "Cap" RESC0603L 5308,1317.88 r90 top (schematic designator C2)
C2_AMP24 "Cap" RESC0603L 5490,1317.88 r90 top (schematic designator C2)
C2_AMP25 "Cap" RESC0603L 5672,1317.88 r90 top (schematic designator C2)
C2_AMP26 "Cap" RESC0603L 5855,1318.35 r90 top (schematic designator C2)
C2_AMP27 "Cap" RESC0603L 6037,1318.35 r90 top (schematic designator C2)
C2_AMP28 "Cap" RESC0603L 6219,1318.35 r90 top (schematic designator C2)
C2_AMP29 "Cap" RESC0603L 6401,1318.35 r90 top (schematic designator C2)
C2_AMP30 "Cap" RESC0603L 6583,1318.78 r90 top (schematic designator C2)
C3_AMP1 "Cap" RESC0603L 1428,1584.78 r90 top (schematic designator C3)
C3_AMP2 "Cap" RESC0603L 1611,1584.78 r90 top (schematic designator C3)
C3_AMP3 "Cap" RESC0603L 1794,1584.78 r90 top (schematic designator C3)
C3_AMP4 "Cap" RESC0603L 1978,1584.78 r90 top (schematic designator C3)
C3_AMP5 "Cap" RESC0603L 2161,1584.78 r90 top (schematic designator C3)
C3_AMP6 "Cap" RESC0603L 2343,1584.78 r90 top (schematic designator C3)
C3_AMP7 "Cap" RESC0603L 2525,1584.78 r90 top (schematic designator C3)
C3_AMP8 "Cap" RESC0603L 2706,1584.78 r90 top (schematic designator C3)
C3_AMP9 "Cap" RESC0603L 2887,1584.78 r90 top (schematic designator C3)
C3_AMP10 "Cap" RESC0603L 3068,1584.78 r90 top (schematic designator C3)
C3_AMP11 "Cap" RESC0603L 3251,1584.78 r90 top (schematic designator C3)
C3_AMP12 "Cap" RESC0603L 3432,1584.78 r90 top (schematic designator C3)
C3_AMP13 "Cap" RESC0603L 3614,1584.78 r90 top (schematic designator C3)
C3_AMP14 "Cap" RESC0603L 3796,1584.78 r90 top (schematic designator C3)
C3_AMP15 "Cap" RESC0603L 3978,1584.78 r90 top (schematic designator C3)
C3_AMP16 "Cap" RESC0603L 4162,1584.78 r90 top (schematic designator C3)
C3_AMP17 "Cap" RESC0603L 4345,1584.78 r90 top (schematic designator C3)
C3_AMP18 "Cap" RESC0603L 4527,1584.78 r90 top (schematic designator C3)
C3_AMP19 "Cap" RESC0603L 4709,1584.78 r90 top (schematic designator C3)
C3_AMP20 "Cap" RESC0603L 4892,1584.78 r90 top (schematic designator C3)
C3_AMP21 "Cap" RESC0603L 5075,1584.88 r90 top (schematic designator C3)
C3_AMP22 "Cap" RESC0603L 5257,1584.88 r90 top (schematic designator C3)
C3_AMP23 "Cap" RESC0603L 5439,1584.88 r90 top (schematic designator C3)
C3_AMP24 "Cap" RESC0603L 5621,1584.88 r90 top (schematic designator C3)
C3_AMP25 "Cap" RESC0603L 5803,1584.88 r90 top (schematic designator C3)
C3_AMP26 "Cap" RESC0603L 5986,1585.35 r90 top (schematic designator C3)
C3_AMP27 "Cap" RESC0603L 6168,1585.35 r90 top (schematic designator C3)
C3_AMP28 "Cap" RESC0603L 6350,1585.35 r90 top (schematic designator C3)
C3_AMP29 "Cap" RESC0603L 6532,1585.35 r90 top (schematic designator C3)
C3_AMP30 "Cap" RESC0603L 6714,1585.78 r90 top (schematic designator C3)
C4_AMP1 "Cap" RESC0603L 1363,1584.78 r90 top (schematic designator C4)
C4_AMP2 "Cap" RESC0603L 1546,1584.78 r90 top (schematic designator C4)
C4_AMP3 "Cap" RESC0603L 1729,1584.78 r90 top (schematic designator C4)
C4_AMP4 "Cap" RESC0603L 1913,1584.78 r90 top (schematic designator C4)
C4_AMP5 "Cap" RESC0603L 2096,1584.78 r90 top (schematic designator C4)
C4_AMP6 "Cap" RESC0603L 2278,1584.78 r90 top (schematic designator C4)
C4_AMP7 "Cap" RESC0603L 2460,1584.78 r90 top (schematic designator C4)
C4_AMP8 "Cap" RESC0603L 2641,1584.78 r90 top (schematic designator C4)
C4_AMP9 "Cap" RESC0603L 2822,1584.78 r90 top (schematic designator C4)
C4_AMP10 "Cap" RESC0603L 3003,1584.78 r90 top (schematic designator C4)
C4_AMP11 "Cap" RESC0603L 3186,1584.78 r90 top (schematic designator C4)
C4_AMP12 "Cap" RESC0603L 3367,1584.78 r90 top (schematic designator C4)
C4_AMP13 "Cap" RESC0603L 3549,1584.78 r90 top (schematic designator C4)
C4_AMP14 "Cap" RESC0603L 3731,1584.78 r90 top (schematic designator C4)
C4_AMP15 "Cap" RESC0603L 3913,1584.78 r90 top (schematic designator C4)
C4_AMP16 "Cap" RESC0603L 4097,1584.78 r90 top (schematic designator C4)
C4_AMP17 "Cap" RESC0603L 4280,1584.78 r90 top (schematic designator C4)
C4_AMP18 "Cap" RESC0603L 4462,1584.78 r90 top (schematic designator C4)
C4_AMP19 "Cap" RESC0603L 4644,1584.78 r90 top (schematic designator C4)
C4_AMP20 "Cap" RESC0603L 4827,1584.78 r90 top (schematic designator C4)
C4_AMP21 "Cap" RESC0603L 5010,1584.88 r90 top (schematic designator C4)
C4_AMP22 "Cap" RESC0603L 5192,1584.88 r90 top (schematic designator C4)
C4_AMP23 "Cap" RESC0603L 5374,1584.88 r90 top (schematic designator C4)
C4_AMP24 "Cap" RESC0603L 5556,1584.88 r90 top (schematic designator C4)
C4_AMP25 "Cap" RESC0603L 5738,1584.88 r90 top (schematic designator C4)
C4_AMP26 "Cap" RESC0603L 5921,1585.35 r90 top (schematic designator C4)
C4_AMP27 "Cap" RESC0603L 6103,1585.35 r90 top (schematic designator C4)
C4_AMP28 "Cap" RESC0603L 6285,1585.35 r90 top (schematic designator C4)
C4_AMP29 "Cap" RESC0603L 6467,1585.35 r90 top (schematic designator C4)
C4_AMP30 "Cap" RESC0603L 6649,1585.78 r90 top (schematic designator C4)
C5_AMP1 "Cap" RESC0603L 1387,1798 r90 top (schematic designator C5)
C5_AMP2 "Cap" RESC0603L 1570,1798 r90 top (schematic designator C5)
C5_AMP3 "Cap" RESC0603L 1753,1798 r90 top (schematic designator C5)
C5_AMP4 "Cap" RESC0603L 1937,1798 r90 top (schematic designator C5)
C5_AMP5 "Cap" RESC0603L 2120,1798 r90 top (schematic designator C5)
C5_AMP6 "Cap" RESC0603L 2302,1798 r90 top (schematic designator C5)
C5_AMP7 "Cap" RESC0603L 2484,1798 r90 top (schematic designator C5)
C5_AMP8 "Cap" RESC0603L 2665,1798 r90 top (schematic designator C5)
C5_AMP9 "Cap" RESC0603L 2846,1798 r90 top (schematic designator C5)
C5_AMP10 "Cap" RESC0603L 3027,1798 r90 top (schematic designator C5)
C5_AMP11 "Cap" RESC0603L 3210,1798 r90 top (schematic designator C5)
C5_AMP12 "Cap" RESC0603L 3391,1798 r90 top (schematic designator C5)
C5_AMP13 "Cap" RESC0603L 3573,1798 r90 top (schematic designator C5)
C5_AMP14 "Cap" RESC0603L 3755,1798 r90 top (schematic designator C5)
C5_AMP15 "Cap" RESC0603L 3937,1798 r90 top (schematic designator C5)
C5_AMP16 "Cap" RESC0603L 4121,1798 r90 top (schematic designator C5)
C5_AMP17 "Cap" RESC0603L 4304,1798 r90 top (schematic designator C5)
C5_AMP18 "Cap" RESC0603L 4486,1798 r90 top (schematic designator C5)
C5_AMP19 "Cap" RESC0603L 4668,1798 r90 top (schematic designator C5)
C5_AMP20 "Cap" RESC0603L 4851,1798 r90 top (schematic designator C5)
C5_AMP21 "Cap" RESC0603L 5034,1798.1 r90 top (schematic designator C5)
C5_AMP22 "Cap" RESC0603L 5216,1798.1 r90 top (schematic designator C5)
C5_AMP23 "Cap" RESC0603L 5398,1798.1 r90 top (schematic designator C5)
C5_AMP24 "Cap" RESC0603L 5580,1798.1 r90 top (schematic designator C5)
C5_AMP25 "Cap" RESC0603L 5762,1798.1 r90 top (schematic designator C5)
C5_AMP26 "Cap" RESC0603L 5945,1798.57 r90 top (schematic designator C5)
C5_AMP27 "Cap" RESC0603L 6127,1798.57 r90 top (schematic designator C5)
C5_AMP28 "Cap" RESC0603L 6309,1798.57 r90 top (schematic designator C5)
C5_AMP29 "Cap" RESC0603L 6491,1798.57 r90 top (schematic designator C5)
C5_AMP30 "Cap" RESC0603L 6673,1799 r90 top (schematic designator C5)
C5_SUMMER1 "Cap" RESC0603L 1592,2677 r90 top (schematic designator C5)
C5_SUMMER2 "Cap" RESC0603L 2507,2677 r90 top (schematic designator C5)
C5_SUMMER3 "Cap" RESC0603L 3415,2677 r90 top (schematic designator C5)
C5_SUMMER4 "Cap" RESC0603L 4326,2677 r90 top (schematic designator C5)
C5_SUMMER5 "Cap" RESC0603L 5239,2677.1 r90 top (schematic designator C5)
C5_SUMMER6 "Cap" RESC0603L 6150,2677.57 r90 top (schematic designator C5)
C6_AMP1 "Cap" RESC0603L 1432,1872 r270 top (schematic designator C6)
C6_AMP2 "Cap" RESC0603L 1615,1872 r270 top (schematic designator C6)
C6_AMP3 "Cap" RESC0603L 1798,1872 r270 top (schematic designator C6)
C6_AMP4 "Cap" RESC0603L 1982,1872 r270 top (schematic designator C6)
C6_AMP5 "Cap" RESC0603L 2165,1872 r270 top (schematic designator C6)
C6_AMP6 "Cap" RESC0603L 2347,1872 r270 top (schematic designator C6)
C6_AMP7 "Cap" RESC0603L 2529,1872 r270 top (schematic designator C6)
C6_AMP8 "Cap" RESC0603L 2710,1872 r270 top (schematic designator C6)
C6_AMP9 "Cap" RESC0603L 2891,1872 r270 top (schematic designator C6)
C6_AMP10 "Cap" RESC0603L 3072,1872 r270 top (schematic designator C6)
C6_AMP11 "Cap" RESC0603L 3255,1872 r270 top (schematic designator C6)
C6_AMP12 "Cap" RESC0603L 3436,1872 r270 top (schematic designator C6)
C6_AMP13 "Cap" RESC0603L 3618,1872 r270 top (schematic designator C6)
C6_AMP14 "Cap" RESC0603L 3800,1872 r270 top (schematic designator C6)
C6_AMP15 "Cap" RESC0603L 3982,1872 r270 top (schematic designator C6)
C6_AMP16 "Cap" RESC0603L 4166,1872 r270 top (schematic designator C6)
C6_AMP17 "Cap" RESC0603L 4349,1872 r270 top (schematic designator C6)
C6_AMP18 "Cap" RESC0603L 4531,1872 r270 top (schematic designator C6)
C6_AMP19 "Cap" RESC0603L 4713,1872 r270 top (schematic designator C6)
C6_AMP20 "Cap" RESC0603L 4896,1872 r270 top (schematic designator C6)
C6_AMP21 "Cap" RESC0603L 5079,1872.1 r270 top (schematic designator C6)
C6_AMP22 "Cap" RESC0603L 5261,1872.1 r270 top (schematic designator C6)
C6_AMP23 "Cap" RESC0603L 5443,1872.1 r270 top (schematic designator C6)
C6_AMP24 "Cap" RESC0603L 5625,1872.1 r270 top (schematic designator C6)
C6_AMP25 "Cap" RESC0603L 5807,1872.1 r270 top (schematic designator C6)
C6_AMP26 "Cap" RESC0603L 5990,1872.57 r270 top (schematic designator C6)
C6_AMP27 "Cap" RESC0603L 6172,1872.57 r270 top (schematic designator C6)
C6_AMP28 "Cap" RESC0603L 6354,1872.57 r270 top (schematic designator C6)
C6_AMP29 "Cap" RESC0603L 6536,1872.57 r270 top (schematic designator C6)
C6_AMP30 "Cap" RESC0603L 6718,1873 r270 top (schematic designator C6)
C7_SUMMER1 "Cap" RESC0603L 1593,2440 r90 top (schematic designator C7)
C7_SUMMER2 "Cap" RESC0603L 2508,2440 r90 top (schematic designator C7)
C7_SUMMER3 "Cap" RESC0603L 3416,2440 r90 top (schematic designator C7)
C7_SUMMER4 "Cap" RESC0603L 4327,2440 r90 top (schematic designator C7)
C7_SUMMER5 "Cap" RESC0603L 5240,2440.1 r90 top (schematic designator C7)
C7_SUMMER6 "Cap" RESC0603L 6151,2440.57 r90 top (schematic designator C7)
C8_SUMMER1 "Cap" RESC0603L 2003,2545 r90 top (schematic designator C8)
C8_SUMMER2 "Cap" RESC0603L 2918,2545 r90 top (schematic designator C8)
C8_SUMMER3 "Cap" RESC0603L 3826,2545 r90 top (schematic designator C8)
C8_SUMMER4 "Cap" RESC0603L 4737,2545 r90 top (schematic designator C8)
C8_SUMMER5 "Cap" RESC0603L 5650,2545.1 r90 top (schematic designator C8)
C8_SUMMER6 "Cap" RESC0603L 6561,2545.57 r90 top (schematic designator C8)
C9_SUMMER1 "Cap" RESC0603L 1265,2655 r90 top (schematic designator C9)
C9_SUMMER2 "Cap" RESC0603L 2180,2655 r90 top (schematic designator C9)
C9_SUMMER3 "Cap" RESC0603L 3088,2655 r90 top (schematic designator C9)
C9_SUMMER4 "Cap" RESC0603L 3999,2655 r90 top (schematic designator C9)
C9_SUMMER5 "Cap" RESC0603L 4912,2655.1 r90 top (schematic designator C9)
C9_SUMMER6 "Cap" RESC0603L 5823,2655.57 r90 top (schematic designator C9)
C10 "Cap" RESC0603L 1755,3205 r0 top
C11 "Cap" RESC0603L 1510,3220 r90 top
CBi_AMP1 "Cap" RESC0603L 1292,1584.78 r90 top (schematic designator CBi)
CBi_AMP2 "Cap" RESC0603L 1475,1584.78 r90 top (schematic designator CBi)
CBi_AMP3 "Cap" RESC0603L 1658,1584.78 r90 top (schematic designator CBi)
CBi_AMP4 "Cap" RESC0603L 1842,1584.78 r90 top (schematic designator CBi)
CBi_AMP5 "Cap" RESC0603L 2025,1584.78 r90 top (schematic designator CBi)
CBi_AMP6 "Cap" RESC0603L 2207,1584.78 r90 top (schematic designator CBi)
CBi_AMP7 "Cap" RESC0603L 2389,1584.78 r90 top (schematic designator CBi)
CBi_AMP8 "Cap" RESC0603L 2570,1584.78 r90 top (schematic designator CBi)
CBi_AMP9 "Cap" RESC0603L 2751,1584.78 r90 top (schematic designator CBi)
CBi_AMP10 "Cap" RESC0603L 2932,1584.78 r90 top (schematic designator CBi)
CBi_AMP11 "Cap" RESC0603L 3115,1584.78 r90 top (schematic designator CBi)
CBi_AMP12 "Cap" RESC0603L 3296,1584.78 r90 top (schematic designator CBi)
CBi_AMP13 "Cap" RESC0603L 3478,1584.78 r90 top (schematic designator CBi)
CBi_AMP14 "Cap" RESC0603L 3660,1584.78 r90 top (schematic designator CBi)
CBi_AMP15 "Cap" RESC0603L 3842,1584.78 r90 top (schematic designator CBi)
CBi_AMP16 "Cap" RESC0603L 4026,1584.78 r90 top (schematic designator CBi)
CBi_AMP17 "Cap" RESC0603L 4209,1584.78 r90 top (schematic designator CBi)
CBi_AMP18 "Cap" RESC0603L 4391,1584.78 r90 top (schematic designator CBi)
CBi_AMP19 "Cap" RESC0603L 4573,1584.78 r90 top (schematic designator CBi)
CBi_AMP20 "Cap" RESC0603L 4756,1584.78 r90 top (schematic designator CBi)
CBi_AMP21 "Cap" RESC0603L 4939,1584.88 r90 top (schematic designator CBi)
CBi_AMP22 "Cap" RESC0603L 5121,1584.88 r90 top (schematic designator CBi)
CBi_AMP23 "Cap" RESC0603L 5303,1584.88 r90 top (schematic designator CBi)
CBi_AMP24 "Cap" RESC0603L 5485,1584.88 r90 top (schematic designator CBi)
CBi_AMP25 "Cap" RESC0603L 5667,1584.88 r90 top (schematic designator CBi)
CBi_AMP26 "Cap" RESC0603L 5850,1585.35 r90 top (schematic designator CBi)
CBi_AMP27 "Cap" RESC0603L 6032,1585.35 r90 top (schematic designator CBi)
CBi_AMP28 "Cap" RESC0603L 6214,1585.35 r90 top (schematic designator CBi)
CBi_AMP29 "Cap" RESC0603L 6396,1585.35 r90 top (schematic designator CBi)
CBi_AMP30 "Cap" RESC0603L 6578,1585.78 r90 top (schematic designator CBi)
CBi_SUMMER1 "Cap" RESC0603L 1583,2555 r180 top (schematic designator CBi)
CBi_SUMMER2 "Cap" RESC0603L 2498,2555 r180 top (schematic designator CBi)
CBi_SUMMER3 "Cap" RESC0603L 3406,2555 r180 top (schematic designator CBi)
CBi_SUMMER4 "Cap" RESC0603L 4317,2555 r180 top (schematic designator CBi)
CBi_SUMMER5 "Cap" RESC0603L 5230,2555.1 r180 top (schematic designator CBi)
CBi_SUMMER6 "Cap" RESC0603L 6141,2555.57 r180 top (schematic designator CBi)
CG_SUMMER1 "Cap" RESC0603L 2088,2720 r0 top (schematic designator CG)
CG_SUMMER2 "Cap" RESC0603L 3003,2720 r0 top (schematic designator CG)
CG_SUMMER3 "Cap" RESC0603L 3911,2720 r0 top (schematic designator CG)
CG_SUMMER4 "Cap" RESC0603L 4822,2720 r0 top (schematic designator CG)
CG_SUMMER5 "Cap" RESC0603L 5735,2720.1 r0 top (schematic designator CG)
CG_SUMMER6 "Cap" RESC0603L 6646,2720.57 r0 top (schematic designator CG)
D1 "D Zener 5.1V" SOT23 6005,3130 r90 top
M1_SUMMER1 "MOSFET-N" SOT-143 1963,2710 r180 top (schematic designator M1)
M1_SUMMER2 "MOSFET-N" SOT-143 2878,2710 r180 top (schematic designator M1)
M1_SUMMER3 "MOSFET-N" SOT-143 3786,2710 r180 top (schematic designator M1)
M1_SUMMER4 "MOSFET-N" SOT-143 4697,2710 r180 top (schematic designator M1)
M1_SUMMER5 "MOSFET-N" SOT-143 5610,2710.1 r180 top (schematic designator M1)
M1_SUMMER6 "MOSFET-N" SOT-143 6521,2710.57 r180 top (schematic designator M1)
P1 "DIN41612 96 pin, Backplane" EURO2.54-2H96 4025,3910 r0 top
Q0_AMP1 "BFR92P" SOT23_N 1360,1480 r0 top (schematic designator Q0)
Q0_AMP2 "BFR92P" SOT23_N 1543,1480 r0 top (schematic designator Q0)
Q0_AMP3 "BFR92P" SOT23_N 1726,1480 r0 top (schematic designator Q0)
Q0_AMP4 "BFR92P" SOT23_N 1910,1480 r0 top (schematic designator Q0)
Q0_AMP5 "BFR92P" SOT23_N 2093,1480 r0 top (schematic designator Q0)
Q0_AMP6 "BFR92P" SOT23_N 2275,1480 r0 top (schematic designator Q0)
Q0_AMP7 "BFR92P" SOT23_N 2457,1480 r0 top (schematic designator Q0)
Q0_AMP8 "BFR92P" SOT23_N 2638,1480 r0 top (schematic designator Q0)
Q0_AMP9 "BFR92P" SOT23_N 2819,1480 r0 top (schematic designator Q0)
Q0_AMP10 "BFR92P" SOT23_N 3000,1480 r0 top (schematic designator Q0)
Q0_AMP11 "BFR92P" SOT23_N 3183,1480 r0 top (schematic designator Q0)
Q0_AMP12 "BFR92P" SOT23_N 3364,1480 r0 top (schematic designator Q0)
Q0_AMP13 "BFR92P" SOT23_N 3546,1480 r0 top (schematic designator Q0)
Q0_AMP14 "BFR92P" SOT23_N 3728,1480 r0 top (schematic designator Q0)
Q0_AMP15 "BFR92P" SOT23_N 3910,1480 r0 top (schematic designator Q0)
Q0_AMP16 "BFR92P" SOT23_N 4094,1480 r0 top (schematic designator Q0)
Q0_AMP17 "BFR92P" SOT23_N 4277,1480 r0 top (schematic designator Q0)
Q0_AMP18 "BFR92P" SOT23_N 4459,1480 r0 top (schematic designator Q0)
Q0_AMP19 "BFR92P" SOT23_N 4641,1480 r0 top (schematic designator Q0)
Q0_AMP20 "BFR92P" SOT23_N 4824,1480 r0 top (schematic designator Q0)
Q0_AMP21 "BFR92P" SOT23_N 5007,1480.1 r0 top (schematic designator Q0)
Q0_AMP22 "BFR92P" SOT23_N 5189,1480.1 r0 top (schematic designator Q0)
Q0_AMP23 "BFR92P" SOT23_N 5371,1480.1 r0 top (schematic designator Q0)
Q0_AMP24 "BFR92P" SOT23_N 5553,1480.1 r0 top (schematic designator Q0)
Q0_AMP25 "BFR92P" SOT23_N 5735,1480.1 r0 top (schematic designator Q0)
Q0_AMP26 "BFR92P" SOT23_N 5918,1480.57 r0 top (schematic designator Q0)
Q0_AMP27 "BFR92P" SOT23_N 6100,1480.57 r0 top (schematic designator Q0)
Q0_AMP28 "BFR92P" SOT23_N 6282,1480.57 r0 top (schematic designator Q0)
Q0_AMP29 "BFR92P" SOT23_N 6464,1480.57 r0 top (schematic designator Q0)
Q0_AMP30 "BFR92P" SOT23_N 6646,1481 r0 top (schematic designator Q0)
Q1_AMP1 "BPR92P" SOT23_N 1357,2229 r180 top (schematic designator Q1)
Q1_AMP2 "BPR92P" SOT23_N 1540,2229 r180 top (schematic designator Q1)
Q1_AMP3 "BPR92P" SOT23_N 1723,2229 r180 top (schematic designator Q1)
Q1_AMP4 "BPR92P" SOT23_N 1907,2229 r180 top (schematic designator Q1)
Q1_AMP5 "BPR92P" SOT23_N 2090,2229 r180 top (schematic designator Q1)
Q1_AMP6 "BPR92P" SOT23_N 2272,2229 r180 top (schematic designator Q1)
Q1_AMP7 "BPR92P" SOT23_N 2454,2229 r180 top (schematic designator Q1)
Q1_AMP8 "BPR92P" SOT23_N 2635,2229 r180 top (schematic designator Q1)
Q1_AMP9 "BPR92P" SOT23_N 2816,2229 r180 top (schematic designator Q1)
Q1_AMP10 "BPR92P" SOT23_N 2997,2229 r180 top (schematic designator Q1)
Q1_AMP11 "BPR92P" SOT23_N 3180,2229 r180 top (schematic designator Q1)
Q1_AMP12 "BPR92P" SOT23_N 3361,2229 r180 top (schematic designator Q1)
Q1_AMP13 "BPR92P" SOT23_N 3543,2229 r180 top (schematic designator Q1)
Q1_AMP14 "BPR92P" SOT23_N 3725,2229 r180 top (schematic designator Q1)
Q1_AMP15 "BPR92P" SOT23_N 3907,2229 r180 top (schematic designator Q1)
Q1_AMP16 "BPR92P" SOT23_N 4091,2229 r180 top (schematic designator Q1)
Q1_AMP17 "BPR92P" SOT23_N 4274,2229 r180 top (schematic designator Q1)
Q1_AMP18 "BPR92P" SOT23_N 4456,2229 r180 top (schematic designator Q1)
Q1_AMP19 "BPR92P" SOT23_N 4638,2229 r180 top (schematic designator Q1)
Q1_AMP20 "BPR92P" SOT23_N 4821,2229 r180 top (schematic designator Q1)
Q1_AMP21 "BPR92P" SOT23_N 5004,2229.1 r180 top (schematic designator Q1)
Q1_AMP22 "BPR92P" SOT23_N 5186,2229.1 r180 top (schematic designator Q1)
Q1_AMP23 "BPR92P" SOT23_N 5368,2229.1 r180 top (schematic designator Q1)
Q1_AMP24 "BPR92P" SOT23_N 5550,2229.1 r180 top (schematic designator Q1)
Q1_AMP25 "BPR92P" SOT23_N 5732,2229.1 r180 top (schematic designator Q1)
Q1_AMP26 "BPR92P" SOT23_N 5915,2229.57 r180 top (schematic designator Q1)
Q1_AMP27 "BPR92P" SOT23_N 6097,2229.57 r180 top (schematic designator Q1)
Q1_AMP28 "BPR92P" SOT23_N 6279,2229.57 r180 top (schematic designator Q1)
Q1_AMP29 "BPR92P" SOT23_N 6461,2229.57 r180 top (schematic designator Q1)
Q1_AMP30 "BPR92P" SOT23_N 6643,2230 r180 top (schematic designator Q1)
Q2_AMP1 "BFT92W" SOT323_L 1325,1875 r90 top (schematic designator Q2)
Q2_AMP2 "BFT92W" SOT323_L 1508,1875 r90 top (schematic designator Q2)
Q2_AMP3 "BFT92W" SOT323_L 1691,1875 r90 top (schematic designator Q2)
Q2_AMP4 "BFT92W" SOT323_L 1875,1875 r90 top (schematic designator Q2)
Q2_AMP5 "BFT92W" SOT323_L 2058,1875 r90 top (schematic designator Q2)
Q2_AMP6 "BFT92W" SOT323_L 2240,1875 r90 top (schematic designator Q2)
Q2_AMP7 "BFT92W" SOT323_L 2422,1875 r90 top (schematic designator Q2)
Q2_AMP8 "BFT92W" SOT323_L 2603,1875 r90 top (schematic designator Q2)
Q2_AMP9 "BFT92W" SOT323_L 2784,1875 r90 top (schematic designator Q2)
Q2_AMP10 "BFT92W" SOT323_L 2965,1875 r90 top (schematic designator Q2)
Q2_AMP11 "BFT92W" SOT323_L 3148,1875 r90 top (schematic designator Q2)
Q2_AMP12 "BFT92W" SOT323_L 3329,1875 r90 top (schematic designator Q2)
Q2_AMP13 "BFT92W" SOT323_L 3511,1875 r90 top (schematic designator Q2)
Q2_AMP14 "BFT92W" SOT323_L 3693,1875 r90 top (schematic designator Q2)
Q2_AMP15 "BFT92W" SOT323_L 3875,1875 r90 top (schematic designator Q2)
Q2_AMP16 "BFT92W" SOT323_L 4059,1875 r90 top (schematic designator Q2)
Q2_AMP17 "BFT92W" SOT323_L 4242,1875 r90 top (schematic designator Q2)
Q2_AMP18 "BFT92W" SOT323_L 4424,1875 r90 top (schematic designator Q2)
Q2_AMP19 "BFT92W" SOT323_L 4606,1875 r90 top (schematic designator Q2)
Q2_AMP20 "BFT92W" SOT323_L 4789,1875 r90 top (schematic designator Q2)
Q2_AMP21 "BFT92W" SOT323_L 4972,1875.1 r90 top (schematic designator Q2)
Q2_AMP22 "BFT92W" SOT323_L 5154,1875.1 r90 top (schematic designator Q2)
Q2_AMP23 "BFT92W" SOT323_L 5336,1875.1 r90 top (schematic designator Q2)
Q2_AMP24 "BFT92W" SOT323_L 5518,1875.1 r90 top (schematic designator Q2)
Q2_AMP25 "BFT92W" SOT323_L 5700,1875.1 r90 top (schematic designator Q2)
Q2_AMP26 "BFT92W" SOT323_L 5883,1875.57 r90 top (schematic designator Q2)
Q2_AMP27 "BFT92W" SOT323_L 6065,1875.57 r90 top (schematic designator Q2)
Q2_AMP28 "BFT92W" SOT323_L 6247,1875.57 r90 top (schematic designator Q2)
Q2_AMP29 "BFT92W" SOT323_L 6429,1875.57 r90 top (schematic designator Q2)
Q2_AMP30 "BFT92W" SOT323_L 6611,1876 r90 top (schematic designator Q2)
Q3_AMP1 "BFT92W" SOT323_L 1347,2020 r90 top (schematic designator Q3)
Q3_AMP2 "BFT92W" SOT323_L 1530,2020 r90 top (schematic designator Q3)
Q3_AMP3 "BFT92W" SOT323_L 1713,2020 r90 top (schematic designator Q3)
Q3_AMP4 "BFT92W" SOT323_L 1897,2020 r90 top (schematic designator Q3)
Q3_AMP5 "BFT92W" SOT323_L 2080,2020 r90 top (schematic designator Q3)
Q3_AMP6 "BFT92W" SOT323_L 2262,2020 r90 top (schematic designator Q3)
Q3_AMP7 "BFT92W" SOT323_L 2444,2020 r90 top (schematic designator Q3)
Q3_AMP8 "BFT92W" SOT323_L 2625,2020 r90 top (schematic designator Q3)
Q3_AMP9 "BFT92W" SOT323_L 2806,2020 r90 top (schematic designator Q3)
Q3_AMP10 "BFT92W" SOT323_L 2987,2020 r90 top (schematic designator Q3)
Q3_AMP11 "BFT92W" SOT323_L 3170,2020 r90 top (schematic designator Q3)
Q3_AMP12 "BFT92W" SOT323_L 3351,2020 r90 top (schematic designator Q3)
Q3_AMP13 "BFT92W" SOT323_L 3533,2020 r90 top (schematic designator Q3)
Q3_AMP14 "BFT92W" SOT323_L 3715,2020 r90 top (schematic designator Q3)
Q3_AMP15 "BFT92W" SOT323_L 3897,2020 r90 top (schematic designator Q3)
Q3_AMP16 "BFT92W" SOT323_L 4081,2020 r90 top (schematic designator Q3)
Q3_AMP17 "BFT92W" SOT323_L 4264,2020 r90 top (schematic designator Q3)
Q3_AMP18 "BFT92W" SOT323_L 4446,2020 r90 top (schematic designator Q3)
Q3_AMP19 "BFT92W" SOT323_L 4628,2020 r90 top (schematic designator Q3)
Q3_AMP20 "BFT92W" SOT323_L 4811,2020 r90 top (schematic designator Q3)
Q3_AMP21 "BFT92W" SOT323_L 4994,2020.1 r90 top (schematic designator Q3)
Q3_AMP22 "BFT92W" SOT323_L 5176,2020.1 r90 top (schematic designator Q3)
Q3_AMP23 "BFT92W" SOT323_L 5358,2020.1 r90 top (schematic designator Q3)
Q3_AMP24 "BFT92W" SOT323_L 5540,2020.1 r90 top (schematic designator Q3)
Q3_AMP25 "BFT92W" SOT323_L 5722,2020.1 r90 top (schematic designator Q3)
Q3_AMP26 "BFT92W" SOT323_L 5905,2020.57 r90 top (schematic designator Q3)
Q3_AMP27 "BFT92W" SOT323_L 6087,2020.57 r90 top (schematic designator Q3)
Q3_AMP28 "BFT92W" SOT323_L 6269,2020.57 r90 top (schematic designator Q3)
Q3_AMP29 "BFT92W" SOT323_L 6451,2020.57 r90 top (schematic designator Q3)
Q3_AMP30 "BFT92W" SOT323_L 6633,2021 r90 top (schematic designator Q3)
Q4_SUMMER1 "BFR92P" SOT23_N 1693,2520 r0 top (schematic designator Q4)
Q4_SUMMER2 "BFR92P" SOT23_N 2608,2520 r0 top (schematic designator Q4)
Q4_SUMMER3 "BFR92P" SOT23_N 3516,2520 r0 top (schematic designator Q4)
Q4_SUMMER4 "BFR92P" SOT23_N 4427,2520 r0 top (schematic designator Q4)
Q4_SUMMER5 "BFR92P" SOT23_N 5340,2520.1 r0 top (schematic designator Q4)
Q4_SUMMER6 "BFR92P" SOT23_N 6251,2520.57 r0 top (schematic designator Q4)
Q5_SUMMER1 "BFR92P" SOT23_N 1687,2667 r180 top (schematic designator Q5)
Q5_SUMMER2 "BFR92P" SOT23_N 2602,2667 r180 top (schematic designator Q5)
Q5_SUMMER3 "BFR92P" SOT23_N 3510,2667 r180 top (schematic designator Q5)
Q5_SUMMER4 "BFR92P" SOT23_N 4421,2667 r180 top (schematic designator Q5)
Q5_SUMMER5 "BFR92P" SOT23_N 5334,2667.1 r180 top (schematic designator Q5)
Q5_SUMMER6 "BFR92P" SOT23_N 6245,2667.57 r180 top (schematic designator Q5)
Q6_SUMMER1 "BFT92W" SOT323_L 1478,2690 r270 top (schematic designator Q6)
Q6_SUMMER2 "BFT92W" SOT323_L 2393,2690 r270 top (schematic designator Q6)
Q6_SUMMER3 "BFT92W" SOT323_L 3301,2690 r270 top (schematic designator Q6)
Q6_SUMMER4 "BFT92W" SOT323_L 4212,2690 r270 top (schematic designator Q6)
Q6_SUMMER5 "BFT92W" SOT323_L 5125,2690.1 r270 top (schematic designator Q6)
Q6_SUMMER6 "BFT92W" SOT323_L 6036,2690.57 r270 top (schematic designator Q6)
Q7_SUMMER1 "BFT92W" SOT323_L 1413,2575 r270 top (schematic designator Q7)
Q7_SUMMER2 "BFT92W" SOT323_L 2328,2575 r270 top (schematic designator Q7)
Q7_SUMMER3 "BFT92W" SOT323_L 3236,2575 r270 top (schematic designator Q7)
Q7_SUMMER4 "BFT92W" SOT323_L 4147,2575 r270 top (schematic designator Q7)
Q7_SUMMER5 "BFT92W" SOT323_L 5060,2575.1 r270 top (schematic designator Q7)
Q7_SUMMER6 "BFT92W" SOT323_L 5971,2575.57 r270 top (schematic designator Q7)
Q8_SUMMER1 "BFR92P" SOT23_N 1898,2530 r180 top (schematic designator Q8)
Q8_SUMMER2 "BFR92P" SOT23_N 2813,2530 r180 top (schematic designator Q8)
Q8_SUMMER3 "BFR92P" SOT23_N 3721,2530 r180 top (schematic designator Q8)
Q8_SUMMER4 "BFR92P" SOT23_N 4632,2530 r180 top (schematic designator Q8)
Q8_SUMMER5 "BFR92P" SOT23_N 5545,2530.1 r180 top (schematic designator Q8)
Q8_SUMMER6 "BFR92P" SOT23_N 6456,2530.57 r180 top (schematic designator Q8)
R1_AMP1 "Res2" RESC0603L 1327,1317.78 r90 top (schematic designator R1)
R1_AMP2 "Res2" RESC0603L 1510,1317.78 r90 top (schematic designator R1)
R1_AMP3 "Res2" RESC0603L 1693,1317.78 r90 top (schematic designator R1)
R1_AMP4 "Res2" RESC0603L 1877,1317.78 r90 top (schematic designator R1)
R1_AMP5 "Res2" RESC0603L 2060,1317.78 r90 top (schematic designator R1)
R1_AMP6 "Res2" RESC0603L 2242,1317.78 r90 top (schematic designator R1)
R1_AMP7 "Res2" RESC0603L 2424,1317.78 r90 top (schematic designator R1)
R1_AMP8 "Res2" RESC0603L 2605,1317.78 r90 top (schematic designator R1)
R1_AMP9 "Res2" RESC0603L 2786,1317.78 r90 top (schematic designator R1)
R1_AMP10 "Res2" RESC0603L 2967,1317.78 r90 top (schematic designator R1)
R1_AMP11 "Res2" RESC0603L 3150,1317.78 r90 top (schematic designator R1)
R1_AMP12 "Res2" RESC0603L 3331,1317.78 r90 top (schematic designator R1)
